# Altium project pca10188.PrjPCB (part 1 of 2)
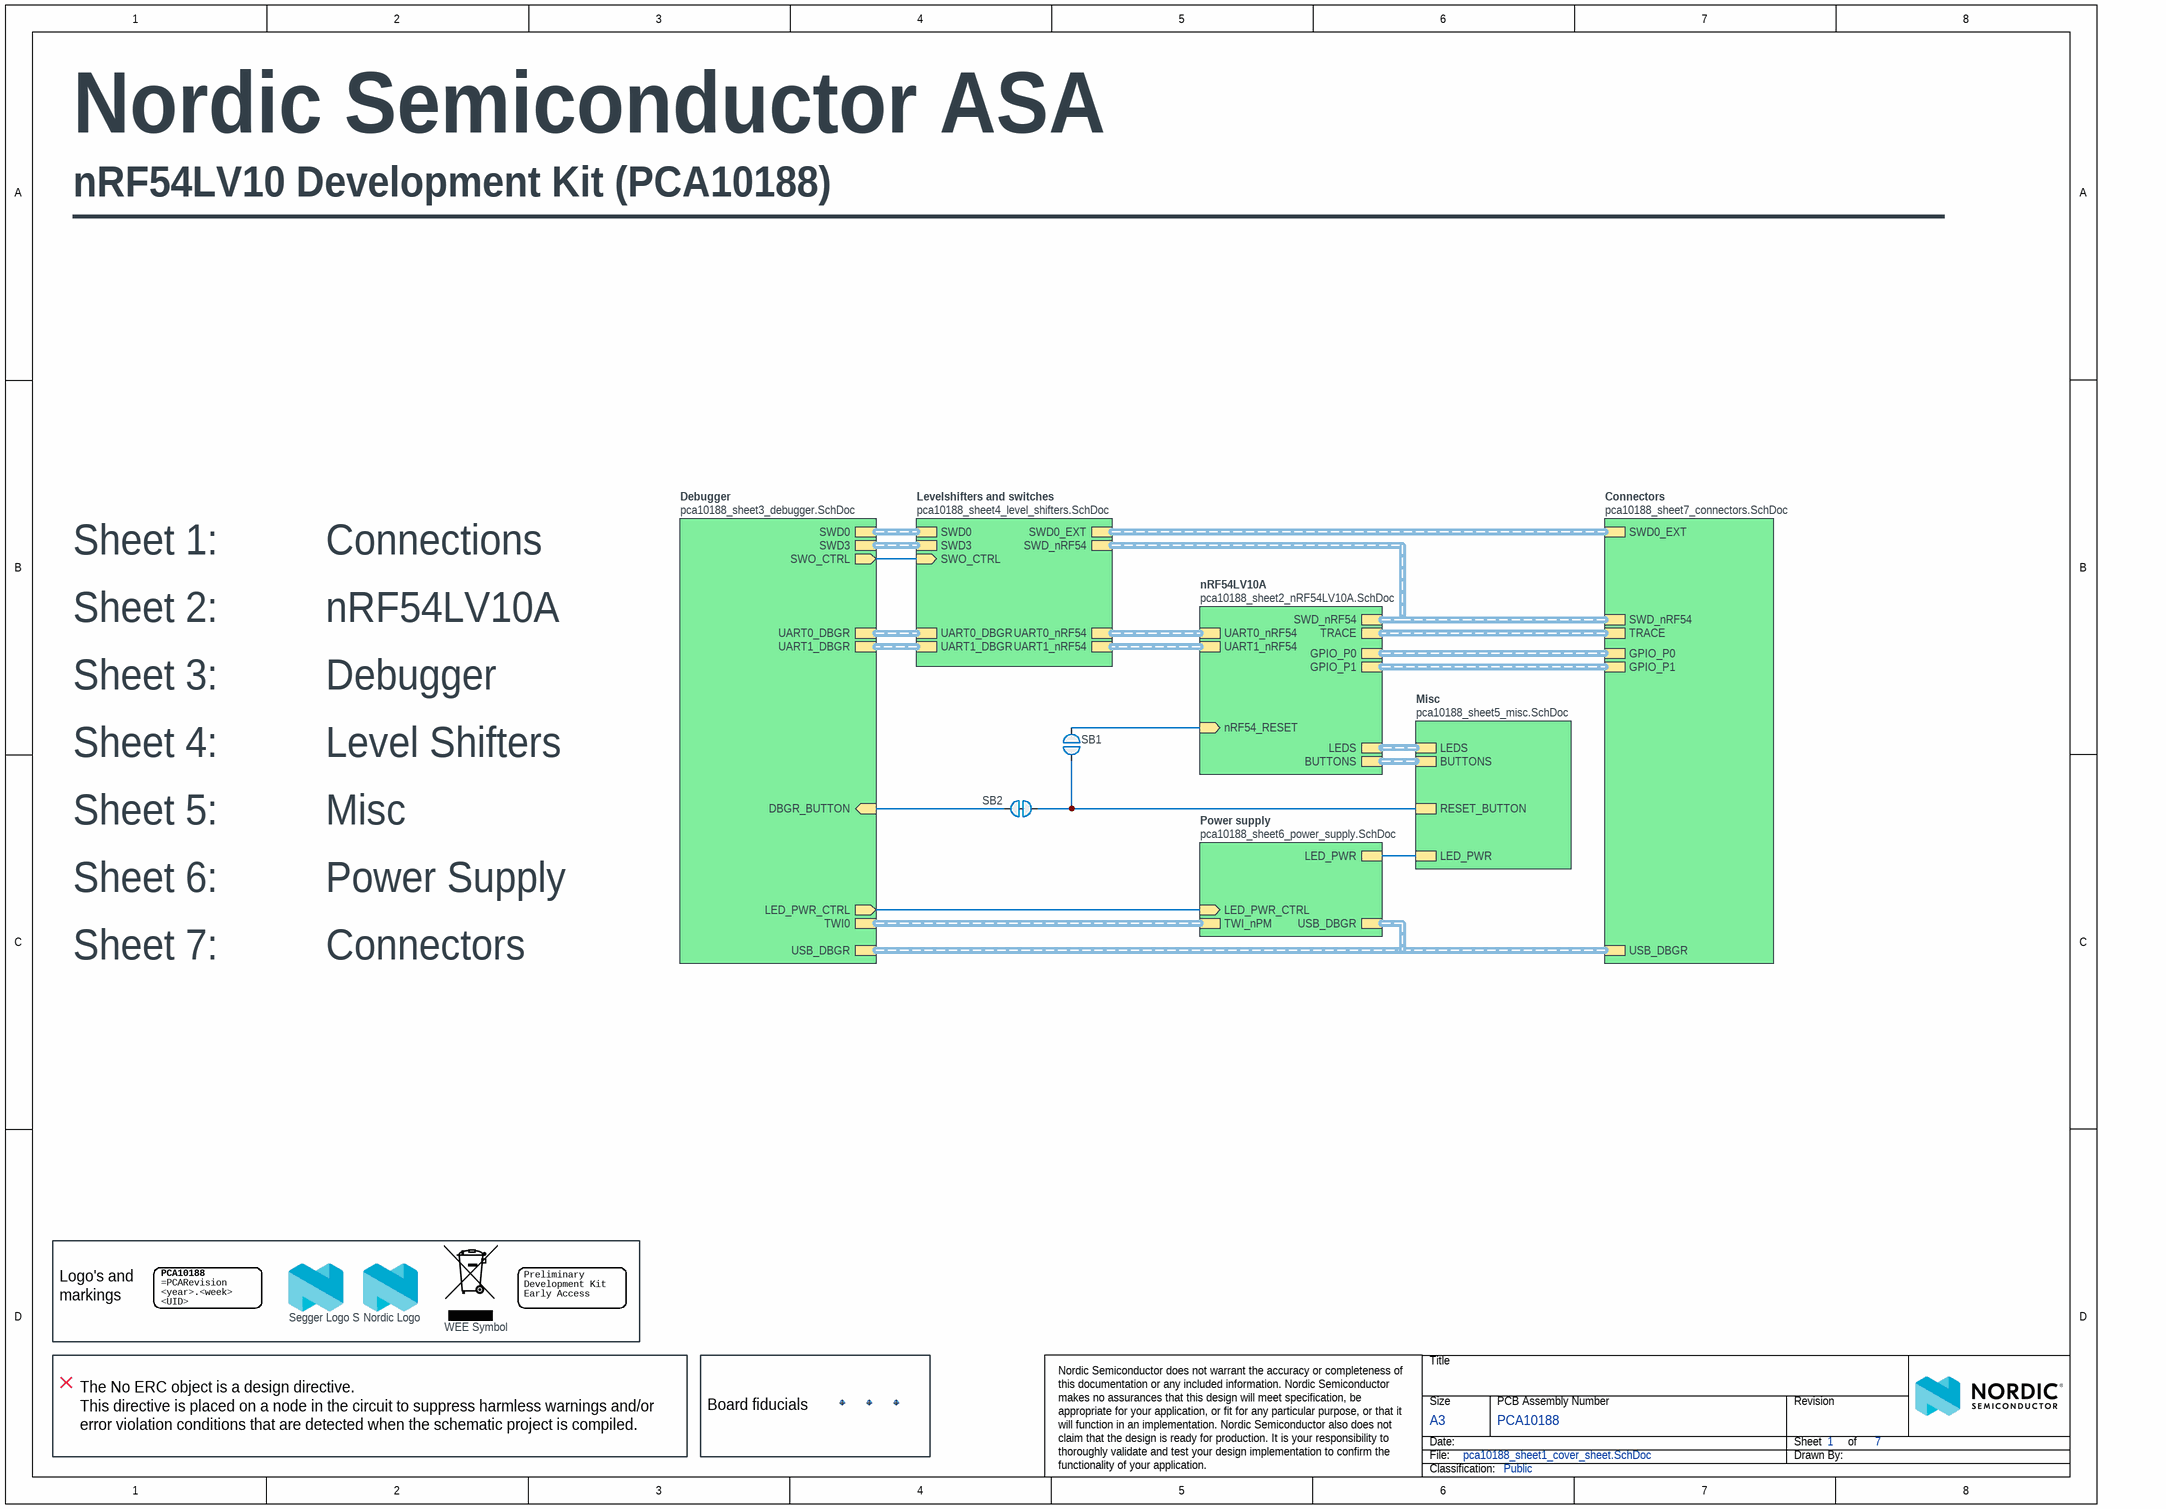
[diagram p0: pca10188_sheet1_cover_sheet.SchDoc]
BoardThickness: 1.6mm; BoardTitle: nRF54LV10-DK; Classification: Public; Compliance: RoHS, REACH, Halogen-Free; Designer: DABA; Dielectric: FR-4 IPC-4101/21; DrawnBy: =Designer; NrOfLayers: 4; Organization: Nordic Semiconductor; PCA_Name: =PCAName; PCAName: PCA10188; PCARevision: 0.7.0; PCBNumber: 400868; PCBRevision: 0038DABA; PCBStackup: 4001; ProductName: nRF54LV10-DK; SilkscreenColor: White; SoldermaskColor: Blue, IPC-SM-840 Class T; SurfaceFinish: ENIG
7 sheets, 211 parts. Net scope: hierarchical (ports join the sheet entries above them; power ports are global).
Board file: 400868.PcbDoc
Sheets:
  pca10188_sheet1_cover_sheet.SchDoc
    nRF54LV10A = pca10188_sheet2_nRF54LV10A.SchDoc
    Debugger = pca10188_sheet3_debugger.SchDoc
    Levelshifters and switches = pca10188_sheet4_level_shifters.SchDoc
    Misc = pca10188_sheet5_misc.SchDoc
    Power supply = pca10188_sheet6_power_supply.SchDoc
    Connectors = pca10188_sheet7_connectors.SchDoc

## Sheet pca10188_sheet1_cover_sheet.SchDoc: =BoardTitle+' - Connections'
size A3; Organization: Nordic Semiconductor; DocumentNumber: 1; Revision: 0.7.0; SheetNumber: 1; SheetTotal: 7; Author: DABA; CompanyName: Nordic Semiconductor; DrawnBy: DABA; DocumentSize: A4

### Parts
Fid1  Fiducial mark  [Fiducial]  (value not drawn)
Fid2  Fiducial mark  [Fiducial]  (value not drawn)
Fid3  Fiducial mark  [Fiducial]  (value not drawn)
LABEL1  12x12mm  [LabelSilk_12x12]  (value not drawn)
LABEL2  20x40mm  [LabelSilk_20x40]  (value not drawn)
LOGO1  Nordic Logo  [NORDIC_LOGO_LYING]  (no BOM)
LOGO2  WEE Symbol  [WEE_3x4.5mm]  (no BOM)
LOGO3  Segger Logo S  [SEGGER_LOGO_S]  (no BOM)
SB1  Solderbridge  [Solderbridge]  (value not drawn)  (no BOM)
SB2  Solderbridge  [Solderbridge_Shorted]  (value not drawn)  (net tie, no BOM)

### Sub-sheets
Connectors = pca10188_sheet7_connectors.SchDoc: SWD_nRF54 (harness SWD), TRACE (harness TRACE), SWD0_EXT (harness SWD), GPIO_P0 (harness GPIO_P0), GPIO_P1 (harness GPIO_P1), USB_DBGR (harness USB)
Debugger = pca10188_sheet3_debugger.SchDoc: DBGR_BUTTON (in), SWD0 (harness SWD), UART0_DBGR (harness UART_IMCU), USB_DBGR (harness USB), UART1_DBGR (harness UART_IMCU), TWI0 (harness TWI), SWD3 (harness SWD), LED_PWR_CTRL (out), SWO_CTRL (out)
Levelshifters and switches = pca10188_sheet4_level_shifters.SchDoc: SWD0 (harness SWD), SWD0_EXT (harness SWD), UART0_nRF54 (harness UART), UART1_nRF54 (harness UART), SWD3 (harness SWD), SWD_nRF54 (harness SWD), UART0_DBGR (harness UART_IMCU), UART1_DBGR (harness UART_IMCU), SWO_CTRL (in)
Misc = pca10188_sheet5_misc.SchDoc: BUTTONS (harness UI), LEDS (harness UI), RESET_BUTTON, LED_PWR
nRF54LV10A = pca10188_sheet2_nRF54LV10A.SchDoc: BUTTONS (harness UI), LEDS (harness UI), TRACE (harness TRACE), GPIO_P0 (harness GPIO_P0), UART0_nRF54 (harness UART), GPIO_P1 (harness GPIO_P1), UART1_nRF54 (harness UART), SWD_nRF54 (harness SWD), nRF54_RESET (in)
Power supply = pca10188_sheet6_power_supply.SchDoc: TWI_nPM (harness TWI), LED_PWR_CTRL (in), LED_PWR, USB_DBGR (harness USB)

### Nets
DBGR_BUTTON: SB2.2 ; sheet Debugger/DBGR_BUTTON
LED_PWR: sheet Misc/LED_PWR, sheet Power supply/LED_PWR
LED_PWR_CTRL: sheet Debugger/LED_PWR_CTRL, sheet Power supply/LED_PWR_CTRL
nRF54_NRESET: SB1.1 ; sheet nRF54LV10A/nRF54_RESET
RESET_BUTTON: SB1.2 SB2.1 ; sheet Misc/RESET_BUTTON
SWO_CTRL: sheet Debugger/SWO_CTRL, sheet Levelshifters and switches/SWO_CTRL

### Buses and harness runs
harness sheet Connectors/GPIO_P0 = sheet nRF54LV10A/GPIO_P0
harness sheet Connectors/GPIO_P1 = sheet nRF54LV10A/GPIO_P1
harness sheet Connectors/SWD0_EXT = sheet Levelshifters and switches/SWD0_EXT
harness sheet Connectors/SWD_nRF54 = sheet Levelshifters and switches/SWD_nRF54 = sheet nRF54LV10A/SWD_nRF54
harness sheet Connectors/TRACE = sheet nRF54LV10A/TRACE
harness sheet Connectors/USB_DBGR = sheet Debugger/USB_DBGR = sheet Power supply/USB_DBGR
harness sheet Debugger/SWD0 = sheet Levelshifters and switches/SWD0
harness sheet Debugger/SWD3 = sheet Levelshifters and switches/SWD3
harness sheet Debugger/TWI0 = sheet Power supply/TWI_nPM
harness sheet Debugger/UART0_DBGR = sheet Levelshifters and switches/UART0_DBGR
harness sheet Debugger/UART1_DBGR = sheet Levelshifters and switches/UART1_DBGR
harness sheet Levelshifters and switches/UART0_nRF54 = sheet nRF54LV10A/UART0_nRF54
harness sheet Levelshifters and switches/UART1_nRF54 = sheet nRF54LV10A/UART1_nRF54
harness sheet Misc/BUTTONS = sheet nRF54LV10A/BUTTONS
harness sheet Misc/LEDS = sheet nRF54LV10A/LEDS

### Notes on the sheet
- Nordic Semiconductor ASA
- nRF54LV10 Development Kit (PCA10188)
- ________________________________________________________________
- Sheet 1:          Connections
- Sheet 2:          nRF54LV10A
- Sheet 3:          Debugger
- Sheet 4:          Level Shifters
- Sheet 5:          Misc
- Sheet 6:          Power Supply
- Sheet 7:          Connectors
- (near LABEL1) Logo's and markings
- The No ERC object is a design directive.
  This directive is placed on a node in the circuit to suppress harmless warnings and/or error violation conditions that are detected when the schematic project is compiled.
- (near Fid1) Board fiducials

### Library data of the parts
Fid1-Fid3 = Fid-Mark: Manufacturer: N.A.; Part number NEMS: 100500073; Value: N.A.; Pad Count: 1; Component Status: Active; System: Connector
LABEL1 = Label_12x12: PCA version label, stick-on, 12x12mm; Manufacturer: Ellco Etikett; Manufacturer Part Number: A33512‐01; Part number NEMS: 101200028; Component Status: Active; Pad Count: 0; Note: N.A.
LABEL2 = Label_20x40: Early Access Label; Manufacturer: NA; Part number NEMS: 101200035; Component Status: Active; Pad Count: 0; Note: N.A.
LOGO1 = Nordic Logo lying: Manufacturer: N.A.; Part number NEMS: 101100001; Component Status: Active; Pad Count: 0
LOGO2 = WEEE Symbol 3x4.5mm: WEEE Directive symbol; Manufacturer: N.A.; Part number NEMS: 101100006; Component Status: Active; Pad Count: 0
LOGO3 = Segger Logo S: Segger logo, small size; Manufacturer: N.A.; Part number NEMS: 101100004; Component Status: Active; Pad Count: 0
SB1 = Solderbridge: Manufacturer: N.A.; Part number NEMS: 100500458; Pad Count: 2; Component Status: Active; System: Connector
SB2 = Solderbridge Shorted: Shorted Solderbridge; Manufacturer: N.A.; Part number NEMS: 100500459; Pad Count: 2; Component Status: Active; System: Connector

## Sheet pca10188_sheet2_nRF54LV10A.SchDoc: =BoardTitle+' - nRF54LV10A'
size A3; Organization: Nordic Semiconductor; DocumentNumber: 2; Revision: 0.7.0; SheetNumber: 2; SheetTotal: 7; Author: DABA; CompanyName: Nordic Semiconductor; DrawnBy: DABA; DocumentSize: A4
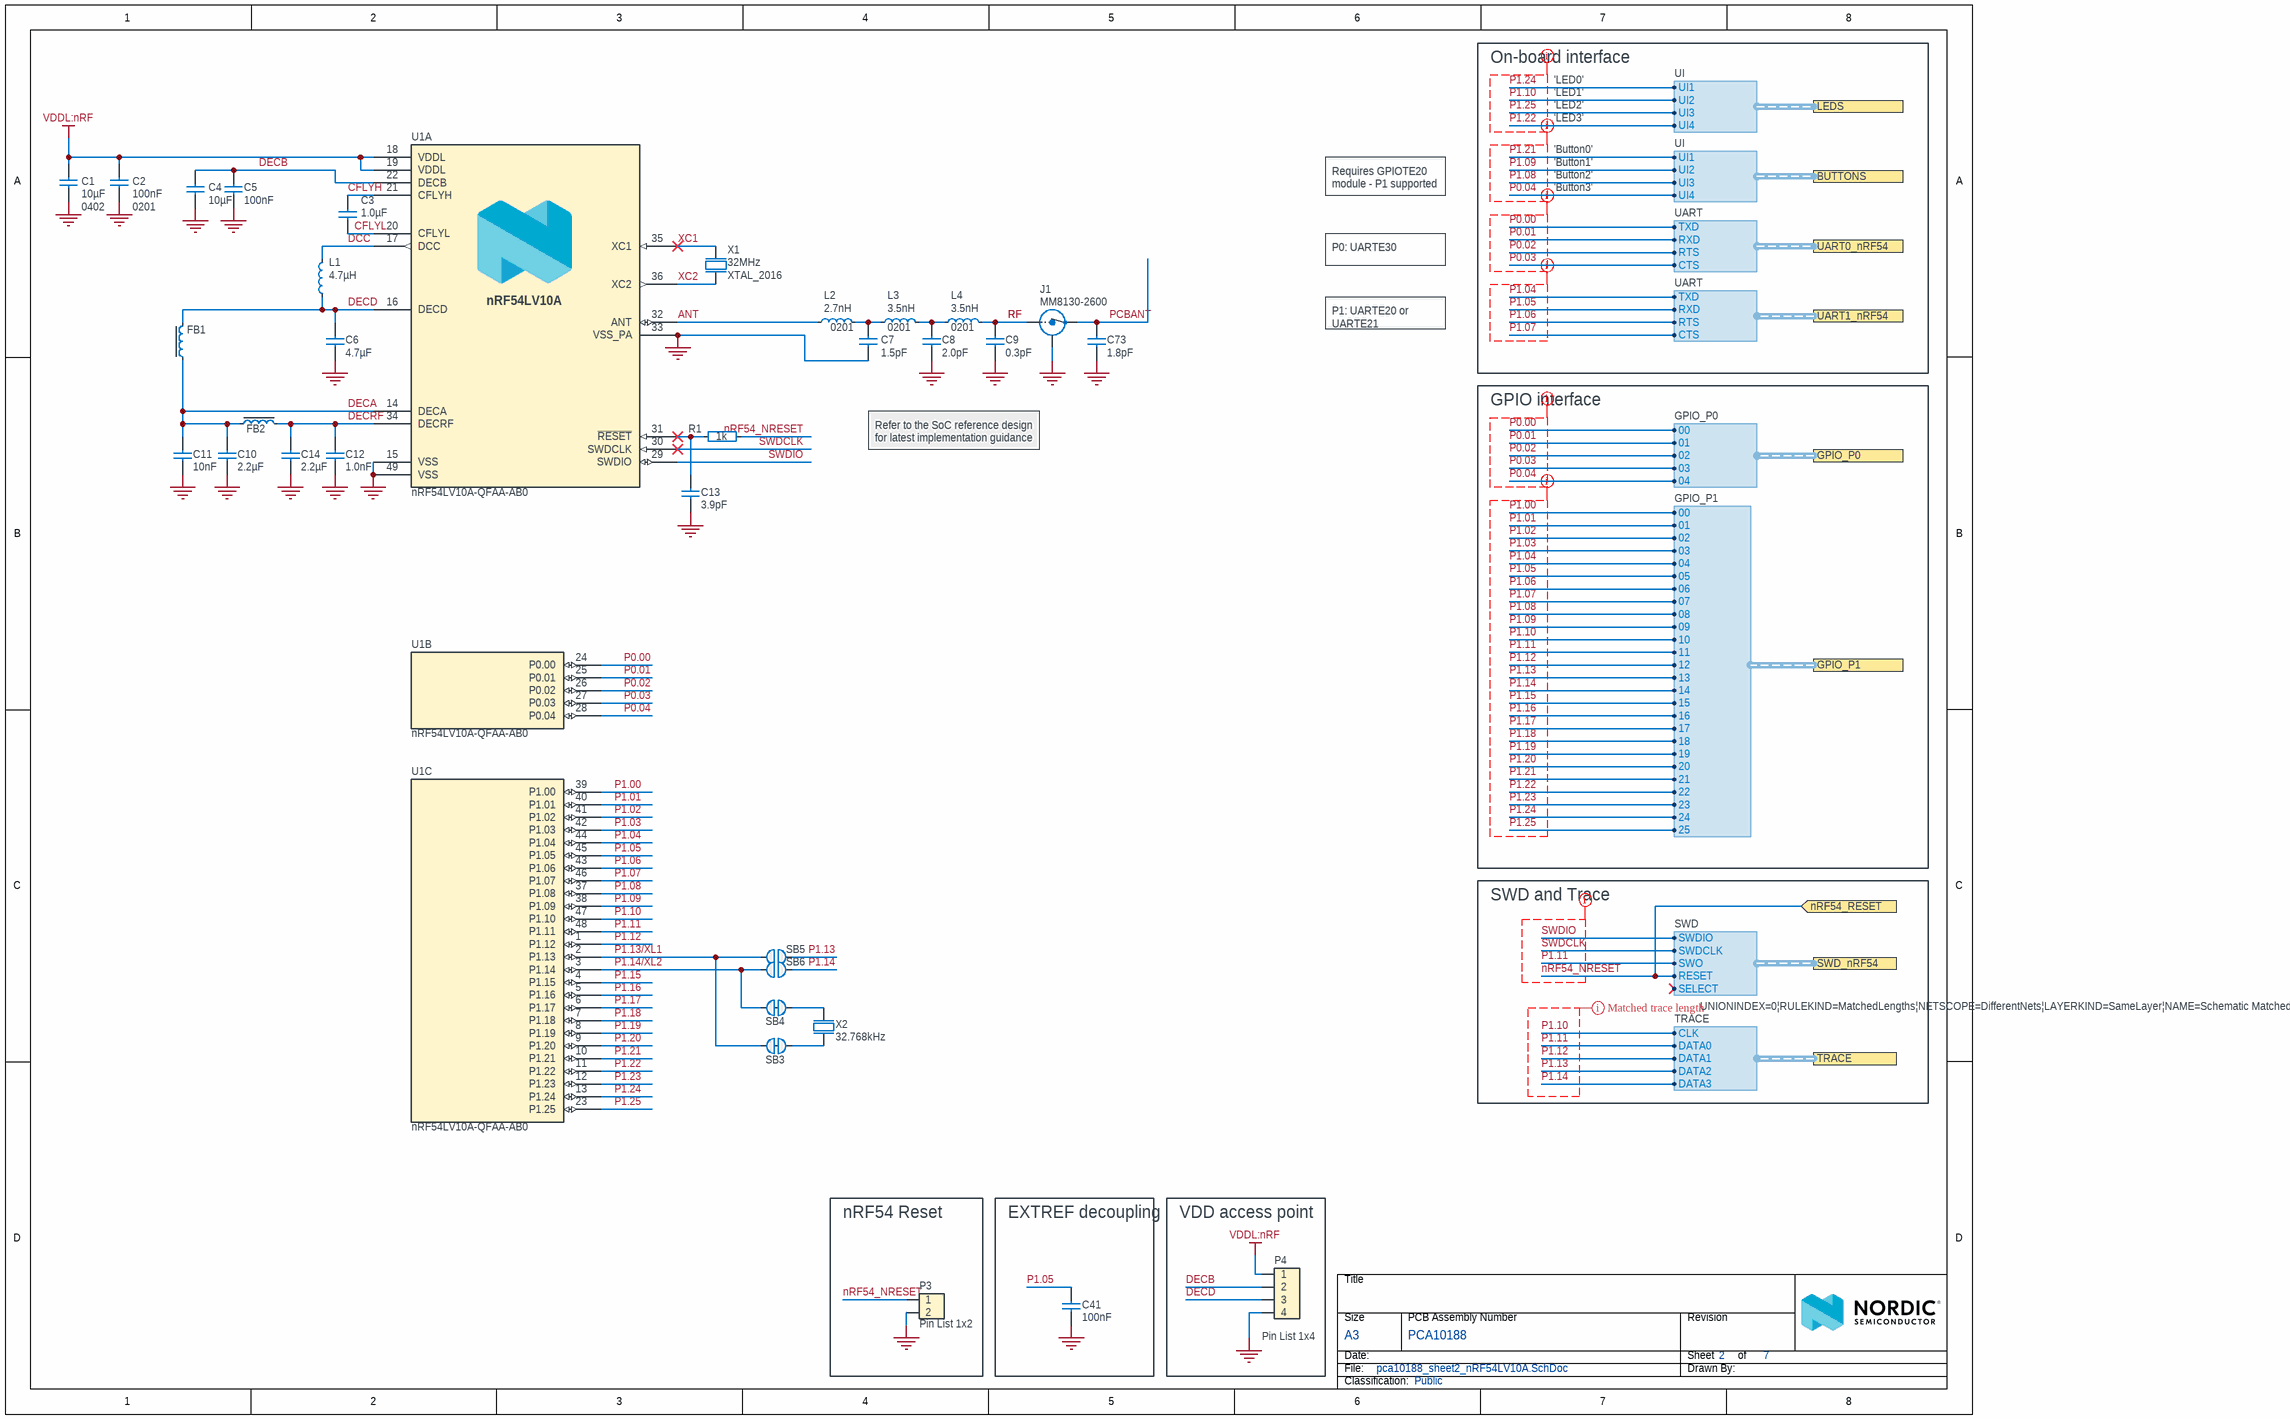
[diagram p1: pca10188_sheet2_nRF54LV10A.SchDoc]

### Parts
C1  10µF  Footprint Doc: 0402  [CAPC1005X04L]
C2  100nF  Footprint Doc: 0201  [CAPC0603X03L_C]
C3  1.0µF  [CAPC0603X03L_C]
C4  10µF  [CAPC1005X04L]
C5  100nF  [CAPC0603X03L_C]
C6  4.7µF  [CAPC0603X03L_C]
C7  1.5pF  [CAPC0603X03L_C]
C8  2.0pF  [CAPC0603X03L_C]
C9  0.3pF  [CAPC0603X03L_C]
C10  2.2µF  [CAPC0603X03L_C]
C11  10nF  [CAPC0603X03L_C]
C12  1.0nF  [CAPC0603X03L_C]
C13  3.9pF  [CAPC0603X03L_C]
C14  2.2µF  [CAPC0603X03L_C]
C41  100nF  [CAPC1005X04L]
C73  1.8pF  [CAPC0603X03L_C]
FB1  120R/0.2A  [INDC0603X03L_C]  (value not drawn)
FB2  120R/0.2A  [INDC0603X03L_C]  (value not drawn)
J1  MM8130-2600  [COAXIAL-SWF]
L1  4.7µH  [INDC1608X06L]
L2  2.7nH  Footprint Doc: 0201  [INDC0603X03L_C]
L3  3.5nH  Footprint Doc: 0201  [INDC0603X03L_C]
L4  3.5nH  Footprint Doc: 0201  [INDC0603X03L_C]
P3  Pin List 1x2  [LIST_1x2]
P4  Pin List 1x4  [LIST_1x4]
R1  1k  [RESC0603X03L_C]
SB3  Solderbridge  [Solderbridge_SHORTED_0.4]  (value not drawn)  (net tie, no BOM)
SB4  Solderbridge  [Solderbridge_SHORTED_0.4]  (value not drawn)  (net tie, no BOM)
SB5  Solderbridge  [Solderbridge_0.4]  (value not drawn)  (no BOM)
SB6  Solderbridge  [Solderbridge_0.4]  (value not drawn)  (no BOM)
U1  nRF54LV10A-QFAA-AB0  [QFN49P40_600x600x90L40x20T460N]  (parts A,B,C of 3)
X1  32MHz  Footprint Doc: XTAL_2016  [BT-XTAL_2016]
X2  32.768kHz  [XTAL_2012]

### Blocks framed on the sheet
nRF54 Reset: P3
EXTREF decoupling: C41
VDD access point: P4

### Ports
BUTTONS (harness UI), GPIO_P0 (harness GPIO_P0), GPIO_P1 (harness GPIO_P1), LEDS (harness UI), nRF54_RESET (in), SWD_nRF54 (harness SWD), TRACE (harness TRACE), UART0_nRF54 (harness UART), UART1_nRF54 (harness UART)

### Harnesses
SWD: SWDIO, SWDCLK, SWO, RESET, SELECT
UART: RTS, CTS, RXD, TXD
GPIO_P1: 00, 01, 02, 03, 04, 05, 06, 07, 08, 09, 10, 11, 12, 13, 14, 15, 21, 22, 16, 23, 17, 24, 18, 25, 19, 20
GPIO_P0: 02, 03, 04, 00, 01
TRACE: CLK, DATA0, DATA1, DATA3, DATA2
UI: UI2, UI1, UI3, UI4

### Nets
GND: C1.1 C2.1 C4.1 C5.2 C6.1 C7.1 C8.1 C9.1 C10.1 C11.1 C12.1 C13.1 C14.1 C41.1 C73.1 J1.2(Shield) P3.2 P4.4 U1.15(VSS) U1.33(VSS_PA) U1.49(VSS) X1.2(GND) X1.4(GND)
VDDL:nRF: C1.2 C2.2 P4.1 U1.18(VDDL) U1.19(VDDL)
ANT: L2.1 U1.32(ANT)
CFLYH: C3.2 U1.21(CFLYH)
CFLYL: C3.1 U1.20(CFLYL)
DCC: L1.1 U1.17(DCC)
DECA: C10.2 C11.2 FB1.2 FB2.2 U1.14(DECA)
DECB: C4.2 C5.1 P4.2 U1.22(DECB)
DECD: C6.2 FB1.1 L1.2 P4.3 U1.16(DECD)
DECRF: C12.2 C14.2 FB2.1 U1.34(DECRF)
nRF54_NRESET: P3.1 R1.2 ; port nRF54_RESET, port SWD_nRF54.RESET
P0.00: U1.24(P0.00) ; port UART0_nRF54.TXD, port GPIO_P0.00
P0.01: U1.25(P0.01) ; port UART0_nRF54.RXD, port GPIO_P0.01
P0.02: U1.26(P0.02) ; port UART0_nRF54.RTS, port GPIO_P0.02
P0.03: U1.27(P0.03) ; port UART0_nRF54.CTS, port GPIO_P0.03
P0.04: U1.28(P0.04) ; port GPIO_P0.04, port BUTTONS.UI4
P1.00: U1.39(P1.00) ; port GPIO_P1.00
P1.01: U1.40(P1.01) ; port GPIO_P1.01
P1.02: U1.41(P1.02) ; port GPIO_P1.02
P1.03: U1.42(P1.03) ; port GPIO_P1.03
P1.04: U1.44(P1.04) ; port GPIO_P1.04, port UART1_nRF54.TXD
P1.05: C41.2 U1.45(P1.05) ; port GPIO_P1.05, port UART1_nRF54.RXD
P1.06: U1.43(P1.06) ; port GPIO_P1.06, port UART1_nRF54.RTS
P1.07: U1.46(P1.07) ; port GPIO_P1.07, port UART1_nRF54.CTS
P1.08: U1.37(P1.08) ; port GPIO_P1.08, port BUTTONS.UI3
P1.09: U1.38(P1.09) ; port GPIO_P1.09, port BUTTONS.UI2
P1.10: U1.47(P1.10) ; port GPIO_P1.10, port TRACE.CLK, port LEDS.UI2
P1.11: U1.48(P1.11) ; port SWD_nRF54.SWO, port GPIO_P1.11, port TRACE.DATA0
P1.12: U1.1(P1.12) ; port GPIO_P1.12, port TRACE.DATA1
P1.13: SB5.2 ; port GPIO_P1.13, port TRACE.DATA2
P1.13/XL1: SB3.1 SB5.1 U1.2(P1.13)
P1.14: SB6.2 ; port GPIO_P1.14, port TRACE.DATA3
P1.14/XL2: SB4.1 SB6.1 U1.3(P1.14)
P1.15: U1.4(P1.15) ; port GPIO_P1.15
P1.16: U1.5(P1.16) ; port GPIO_P1.16
P1.17: U1.6(P1.17) ; port GPIO_P1.17
P1.18: U1.7(P1.18) ; port GPIO_P1.18
P1.19: U1.8(P1.19) ; port GPIO_P1.19
P1.20: U1.9(P1.20) ; port GPIO_P1.20
P1.21: U1.10(P1.21) ; port GPIO_P1.21, port BUTTONS.UI1
P1.22: U1.11(P1.22) ; port GPIO_P1.22, port LEDS.UI4
P1.23: U1.12(P1.23) ; port GPIO_P1.23
P1.24: U1.13(P1.24) ; port GPIO_P1.24, port LEDS.UI1
P1.25: U1.23(P1.25) ; port GPIO_P1.25, port LEDS.UI3
PCBANT: C73.2 J1.3(OUT)
RF: C9.2 J1.1(IN) L4.2
SWDCLK: U1.30(SWDCLK) ; port SWD_nRF54.SWDCLK
SWDIO: U1.29(SWDIO) ; port SWD_nRF54.SWDIO
XC1: U1.35(XC1) X1.1(inp)
XC2: U1.36(XC2) X1.3(out)
NetC7_2: C7.2 L2.2 L3.1
NetC8_2: C8.2 L3.2 L4.1
NetC13_2: C13.2 R1.1 U1.31(~{RESET})
NetSB3_2: SB3.2 X2.2(out)
NetSB4_2: SB4.2 X2.1(inp)

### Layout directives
net class TRACE; rule Matched Net Lengths [Delay Tolerance = 500ps]: P1.10, P1.11, P1.12, P1.13, P1.14
net class LEDS: P1.10, P1.22, P1.24, P1.25
net class UART0: P0.00, P0.01, P0.02, P0.03
net class UART1: P1.04, P1.05, P1.06, P1.07
net class BUTTONS: P0.04, P1.08, P1.09, P1.21
net class SWD_nRF54: nRF54_NRESET, P1.11, SWDCLK, SWDIO
net class GPIO_P0: P0.00, P0.01, P0.02, P0.03, P0.04
net class GPIO_P1: P1.00, P1.01, P1.02, P1.03, P1.04, P1.05, P1.06, P1.07, P1.08, P1.09, P1.10, P1.11, P1.12, P1.13, P1.14, P1.15, P1.16, P1.17, P1.18, P1.19, P1.20, P1.21, P1.22, P1.23, P1.24, P1.25

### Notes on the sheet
- On-board interface
- 'LED1'
- 'LED0'
- 'LED2'
- 'LED3'
- 'Button1'
- 'Button0'
- Requires GPIOTE20 module - P1 supported
- 'Button2'
- 'Button3'
- P0: UARTE30
- P1: UARTE20 or UARTE21
- GPIO interface
- Refer to the SoC reference design for latest implementation guidance
- SWD and Trace

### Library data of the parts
C1 C4 = C0402-10µF-6.3V-X6S: Capacitor, X6S, ±20%, 6.3V; Manufacturer: N.A.; Part number NEMS: 100200478; Component Status: Active; Pad Count: 2
C2 = C0201-100n-10V-X7R: Capacitor, X7R, ±10%, 100nF, 10V; Manufacturer: N.A.; Part number NEMS: 100200469; Component Status: Active; Pad Count: 2
C3 = C0201-1µ0-6.3V: Capacitor, Ceramic, X5R, ±20%, 6.3V; Manufacturer: Murata; Manufacturer Part Number: GRM033R60J105MEA2D; Part number NEMS: 100200387; Component Status: Active; Pad Count: 2; Artikkelnr Noca: N.A.
C5 = C0201-100n-10V-X7R: Capacitor, X7R, ±10%; Manufacturer: N.A.; Part number NEMS: 100200469; Note: 10V; Pad Count: 2; Component Status: Active
C6 = C0201-4.7µ-6V3-X5R-GRM035R60J475ME15J: Capacitor, Ceramic, X5R, ±20%, 6.3V; Manufacturer: Murata; Part number NEMS: 100200685; Component Status: Active; Pad Count: 2; Note: -55°C ~ 85°C; Artikkelnr Noca: N.A.
C7 = C0201-1.5p-25V-NP0-GJM0335C1E1R5WB01: Capacitor, NP0, ±0.05pF, 25V, High Q; Manufacturer: Murata; Part number NEMS: 100200477; Component Status: Active; Pad Count: 2; Artikkelnr Noca: N.A.
C8 = C0201-2.0p-HQ-Murata: Capacitor, NP0, ±0.05pF, 25V; Manufacturer: Murata; Manufacturer Part Number: GJM0335C1E2R0WB01; Part number IPS: 00000001775; Part number NEMS: 100200419; Component Status: Active; Pad Count: 2; Artikkelnr Noca: N.A.
C9 = C0201-0.3p-50V-GRM0335C1HR30BA01: Capacitor, C0G, ±0.1pF, 50V; Manufacturer: Murata; Part number NEMS: 100200650; Component Status: Active; Pad Count: 2; Artikkelnr Noca: N.A.
C10 C14 = C0201-2µ2-2.5V-X6T-GRM033D80E225ME47D: Capacitor, Ceramic, 2.2µF 2.5V X6T 0201,±20%; Manufacturer: Murata; Part number NEMS: 100200527; Component Status: Active; Pad Count: 2; Note: 2.5V, 20%, X6T; Artikkelnr Noca: N.A.
C11 = C0201-10n-6.3V-X7R: Capacitor, X7R, 6.3V; Manufacturer: Murata; Manufacturer Part Number: GRM033R70J103KA01D; Part number NEMS: 100200407; Component Status: Active; Pad Count: 2; Artikkelnr Noca: N.A.
C12 = C0201-1n0: Capacitor, X7R, ±10%, 25V; Manufacturer: N.A.; Part number IPS: 00000003206; Part number NEMS: 100200056; Component Status: Active; Pad Count: 2; Note: 16V
C13 = C0201-3.9p: Chip Cap 0201; Manufacturer: N.A.; Part number NEMS: 100200024,100200424; Component Status: Active; Pad Count: 2; Note: Chip Cap 1%
C41 = C0402-100n: Capacitor, X7R, ±10%; Manufacturer: N.A.; Part number IPS: 00000005296; Part number NEMS: 100200184; Component Status: Active; Pad Count: 2; Note: 16V; Artikkelnr Noca: 20039200
C73 = C0201-1p8-50V-COG-GJM0335C1H1R8BB01: CAP CER 1.8PF 50V C0G/NP0 0201; Manufacturer: Murata; Part number NEMS: 100200681; Pad Count: 2; Note: 50V, ±0,1pF; Artikkelnr Noca: N.A.; Component Status: Active
FB1 FB2 = FB0201-120R@100M-200mA-BLM03AG121SN1D: Ferrite Bead, 120 Ohm @ 100MHz, 200mA, 500 mOhm Max; Manufacturer: Murata; Part number NEMS: 100300419; Component Status: Active; Pad Count: 2; Artikkelnr Noca: N.A.
J1 = MM8130-2600: Coaxial Connector with Switch; Manufacturer: Murata; Part number IPS: 00000009955; Part number Norautron: 26030338; Part number NEMS: 100500400; Component Status: Active; Pad Count: 3; Note: N.A.; Artikkelnr Noca: 55029011
L1 = L0603-4µ7-MLZ1608M4R7WT000: Inductor, 120mA, ±20%, 0.65R; Manufacturer: TDK Corporation; Part number NEMS: 100300440; Component Status: Active; Pad Count: 2; Note: Power Inductor ±20%; Artikkelnr Noca: N.A.
L2 = L0201-2n7-HQ-Murata: Inductor, 600mA, ±0.1ｎH, 120mOhm; Manufacturer: Murata; Manufacturer Part Number: LQP03HQ2N7B02; Part number IPS: 00000001753; Part number NEMS: 100300214; Component Status: Active; Pad Count: 2; Note: -55°C ~ 125°C; Artikkelnr Noca: N.A.
L3 L4 = L0201-3n5-HQ-Murata: Inductor, 500mA, ±0.1ｎH, 170mOhm; Manufacturer: Murata; Manufacturer Part Number: LQP03HQ3N5B02; Part number NEMS: 100300222; Component Status: Active; Pad Count: 2; Note: -55°C ~ 125°C; Artikkelnr Noca: N.A.
P3 = Pin List 1x2: Pin List 1x2, 2.54mm (100mil); Manufacturer: N.A.; Part number NEMS: 100500297; Component Status: Active; Pad Count: 2; Artikkelnr Noca: 56019040; System: Connector
P4 = Pin List 1x4: Pin List 1x4, 2.54mm (100mil); Manufacturer: N.A.; Part number NEMS: 100500309; Component Status: Active; Pad Count: 4; Artikkelnr Noca: 56019092; System: Connector
R1 = R0201-1k0: Resistor, ±1%, 0.05W; Manufacturer: N.A.; Part number IPS: 00000005786; Part number NEMS: 100100043; Component Status: Active; Pad Count: 2; Note: Chip Res 1%
SB3 SB4 = Solderbridge Shorted 0.4mm: Shorted Solderbridge; Manufacturer: N.A.; Part number NEMS: 100500561; Component Status: Active; Pad Count: 2; System: Connector
SB5 SB6 = Solderbridge 0.4mm: Manufacturer: N.A.; Part number NEMS: 100500560; Component Status: Active; Pad Count: 2; System: Connector
U1 = nRF54LV10A-QFAA-AB0: Multi-protocol Bluetooth Low Energy, IEEE 802.15.4 and 2.4GHz proprietary Wireless MCU; Manufacturer: Nordic Semiconductor; Part number NEMS: 102000385; Component Status: Active; Pad Count: 49; Note: N.A.
X1 = XTAL_SMD2016_32MHz_8pF_Kyocera: XTAL SMD 2016, 32MHz, Cl=8pF, Tot: ±40ppm; Manufacturer Part Number: CX2016DB32000D0WZRC1; Part number IPS: 00000007827; Part number Norautron: 26511136; Part number NEMS: 101600039; Component Status: Active; Pad Count: 4; Note: XTAL SMD 32.000MHz; Artikkelnr Noca: 22010022
X2 = XTAL_SMD2012_32.768kHz_9pF_TXC: XTAL SMD 2012, 32.768kHz, 9pF, ±20ppm; Manufacturer: TXC Corporation; Manufacturer Part Number: 9HT11-32.768KDZC-T; Part number NEMS: 101600107; Component Status: Active; Pad Count: 2; Note: XTAL SMD 32.768kHz; Artikkelnr Noca: N.A.

## Sheet pca10188_sheet3_debugger.SchDoc: =BoardTitle+' - Debugger'
size A3; Organization: Nordic Semiconductor; DocumentNumber: 3; Revision: 0.7.0; SheetNumber: 3; SheetTotal: 7; Author: DABA; CompanyName: Nordic Semiconductor; DrawnBy: DABA; DocumentSize: A4
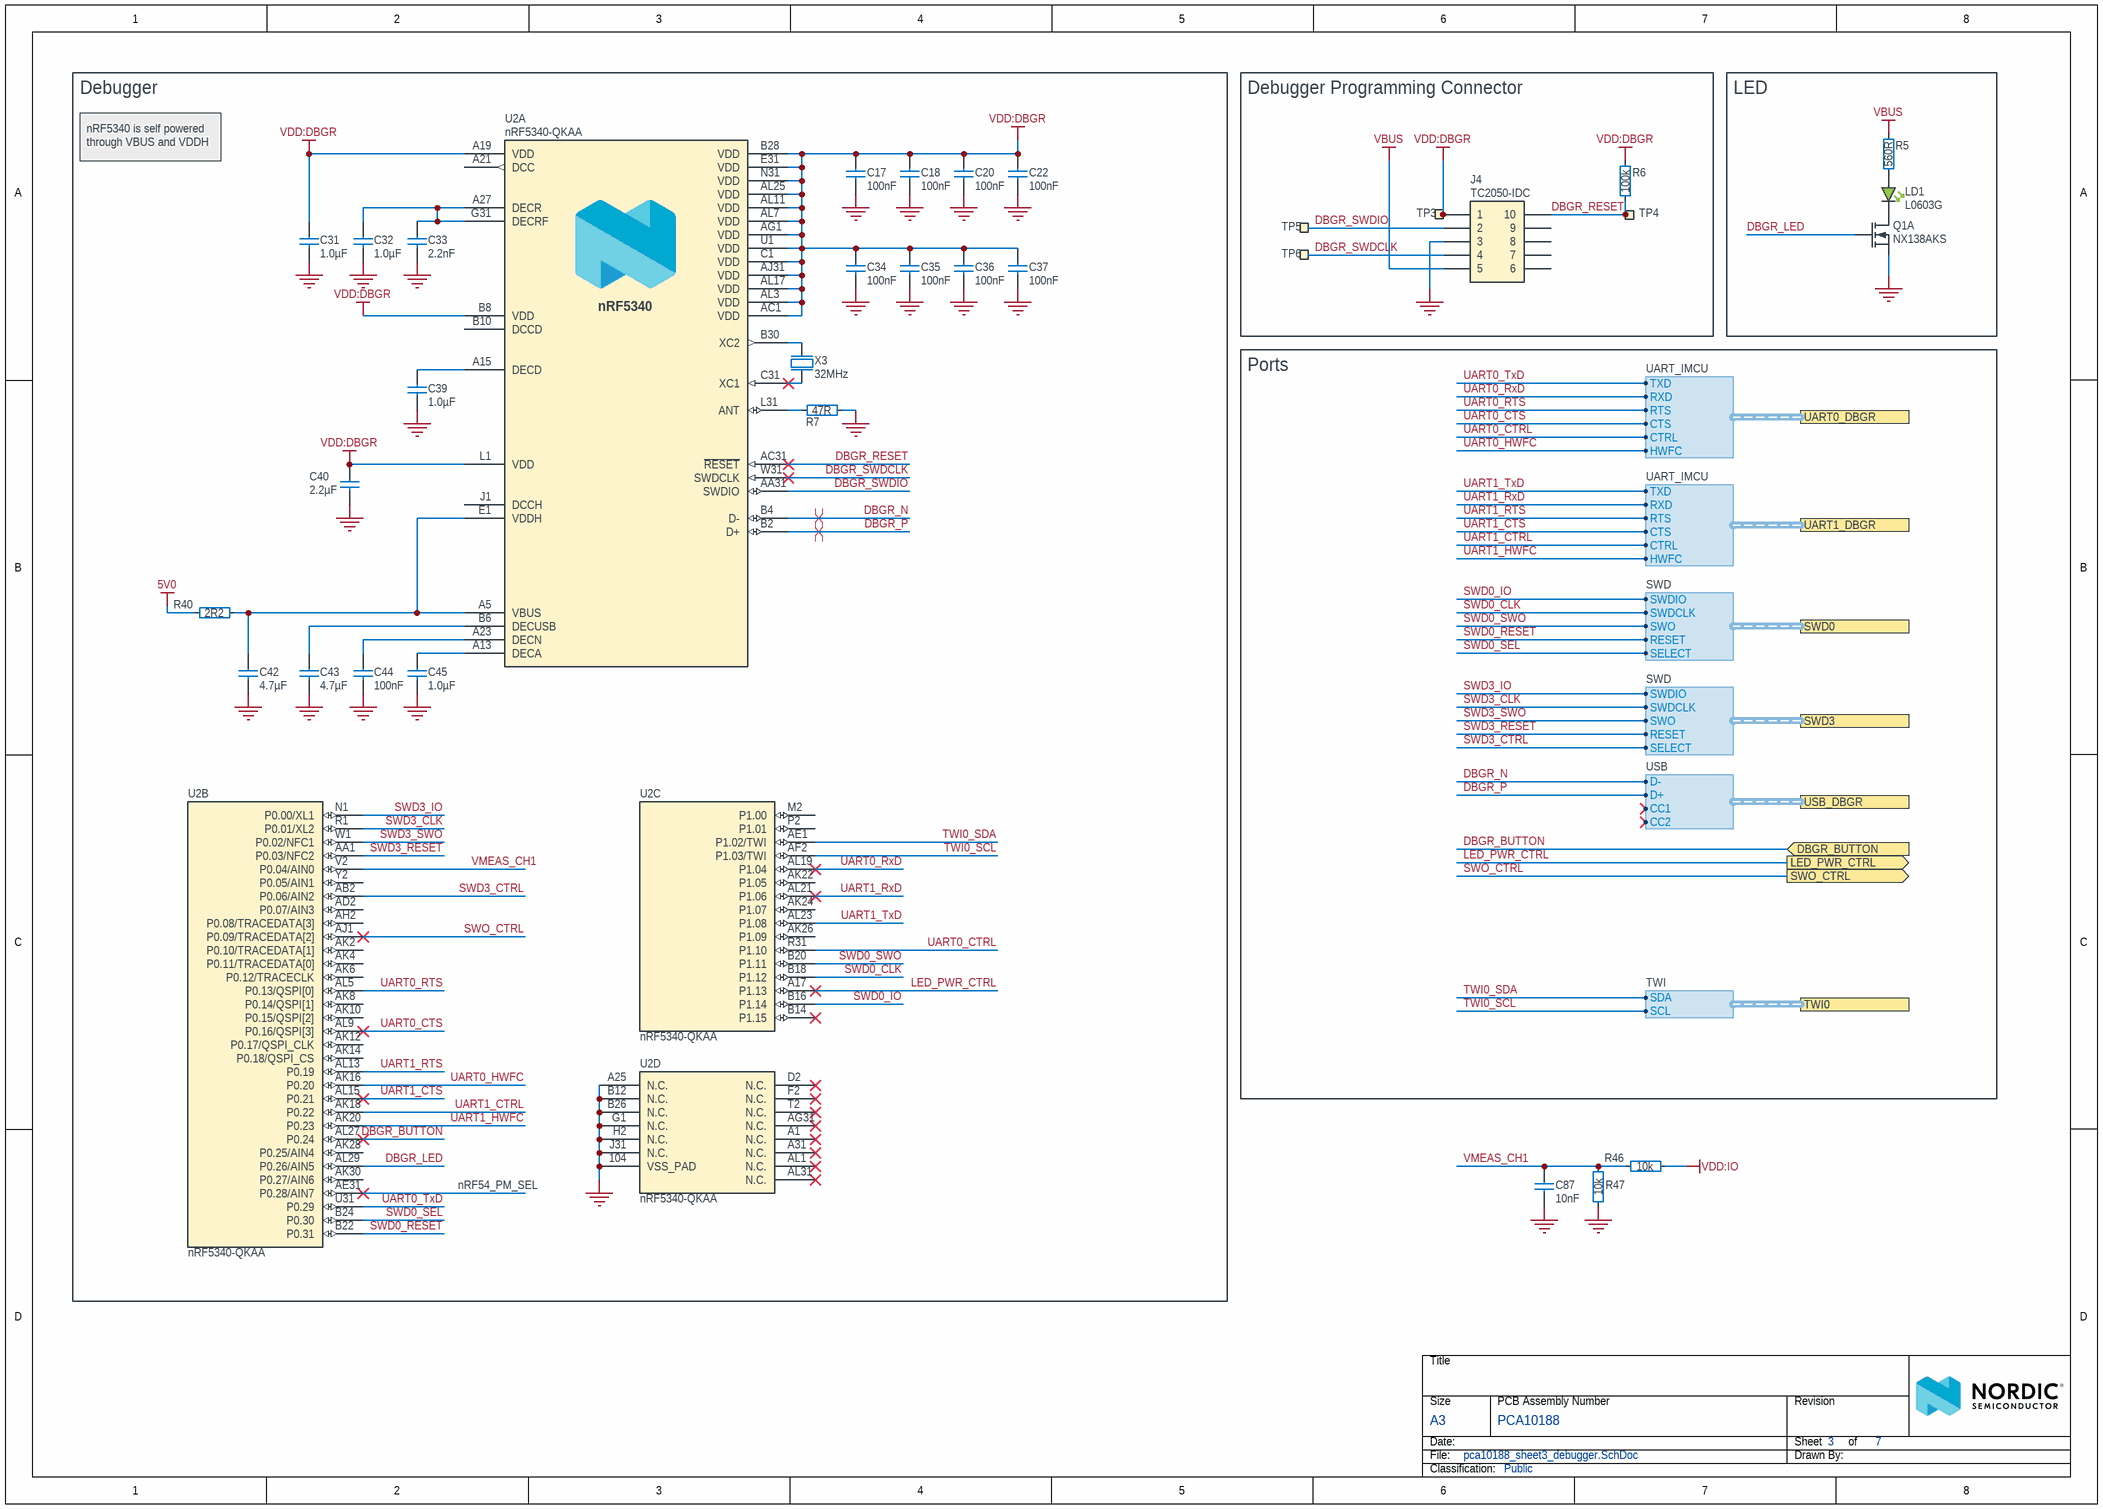
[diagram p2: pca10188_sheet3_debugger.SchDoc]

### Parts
C17  100nF  [CAPC0603X03L_C]
C18  100nF  [CAPC0603X03L_C]
C20  100nF  [CAPC0603X03L_C]
C22  100nF  [CAPC0603X03L_C]
C31  1.0µF  [CAPC1005X04L]
C32  1.0µF  [CAPC1005X04L]
C33  2.2nF  [CAPC0603X03L_C]
C34  100nF  [CAPC0603X03L_C]
C35  100nF  [CAPC0603X03L_C]
C36  100nF  [CAPC0603X03L_C]
C37  100nF  [CAPC0603X03L_C]
C39  1.0µF  [CAPC1005X04L]
C40  2.2µF  [CAPC1608X06L]
C42  4.7µF  [CAPC1608X06L]
C43  4.7µF  [CAPC1608X06L]
C44  100nF  [CAPC0603X03L_C]
C45  1.0µF  [CAPC1005X04L]
C87  10nF  [CAPC0603X03L_C]
J4  TC2050-IDC  [TC2050-IDC-NLFP]  (no BOM)
LD1  L0603G  [LED_0603_G]
Q1  NX138AKS  [TSSOP6]  (part A of 2)
R5  560R  [RESC0603X03L_C]
R6  100k  [RESC0603X03L_C]
R7  47R  [RESC0603X03L_C]
R40  2R2  [RESC1005X04L]
R46  10k  [RESC0603X03L_C]
R47  10k  [RESC0603X03L_C]
TP3  Ø1.5mm,SMD  [TP_SMD_D1.5mm]  (value not drawn)  (no BOM)
TP4  Ø1.5mm,SMD  [TP_SMD_D1.5mm]  (value not drawn)  (no BOM)
TP5  Ø1.5mm,SMD  [TP_SMD_D1.5mm]  (value not drawn)  (no BOM)
TP6  Ø1.5mm,SMD  [TP_SMD_D1.5mm]  (value not drawn)  (no BOM)
U2  nRF5340-QKAA  [AQFN40P700X700X85_HS-99N]  (parts A,B,C,D of 4)
X3  32MHz  [BT-XTAL_2016]

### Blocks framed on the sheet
Debugger: C17 C18 C20 C22 C31-C37 C39 C40 C42-C45 R7 R40 U2 X3
Debugger Programming Connector: J4 R6 TP3-TP6
LED: LD1 Q1 R5

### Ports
DBGR_BUTTON (in), LED_PWR_CTRL (out), SWD0 (harness SWD), SWD3 (harness SWD), SWO_CTRL (out), TWI0 (harness TWI), UART0_DBGR (harness UART_IMCU), UART1_DBGR (harness UART_IMCU), USB_DBGR (harness USB)

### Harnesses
SWD: SWDIO, SWDCLK, SWO, RESET, SELECT
UART_IMCU: RTS, CTS, RXD, TXD, HWFC, CTRL
TWI: SCL, SDA
USB: D+, D-, CC1, CC2

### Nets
5V0: R40.2
GND: C17.2 C18.2 C20.2 C22.2 C31.2 C32.1 C33.2 C34.2 C35.2 C36.2 C37.2 C39.1 C40.2 C42.2 C43.2 C44.2 C45.1 C87.2 J4.3 Q1.1(S1) R7.2 R47.1 U2.104(VSS_PAD) U2.A25(N.C.) U2.B12(N.C.) U2.B26(N.C.) U2.G1(N.C.) U2.H2(N.C.) U2.J31(N.C.) X3.2(GND) X3.4(GND)
VBUS: J4.5 R5.2
VDD:DBGR: C17.1 C18.1 C20.1 C22.1 C31.1 C34.1 C35.1 C36.1 C37.1 C40.1 J4.1 R6.2 TP3.1 U2.A19(VDD) U2.AC1(VDD) U2.AG1(VDD) U2.AJ31(VDD) U2.AL3(VDD) U2.AL7(VDD) U2.AL11(VDD) U2.AL17(VDD) U2.AL25(VDD) U2.B8(VDD) U2.B28(VDD) U2.C1(VDD) U2.E31(VDD) U2.L1(VDD) U2.N31(VDD) U2.U1(VDD)
VDD:IO: R46.2
DBGR_BUTTON: U2.AL27(P0.24) ; port DBGR_BUTTON
DBGR_LED: Q1.2(G1) U2.AL29(P0.26/AIN5)
DBGR_N: U2.B4(D-) ; port USB_DBGR.D-
DBGR_P: U2.B2(D+) ; port USB_DBGR.D+
DBGR_RESET: J4.10 R6.1 TP4.1 U2.AC31(~{RESET})
DBGR_SWDCLK: J4.4 TP6.1 U2.W31(SWDCLK)
DBGR_SWDIO: J4.2 TP5.1 U2.AA31(SWDIO)
LED_PWR_CTRL: U2.A17(P1.13) ; port LED_PWR_CTRL
SWD0_CLK: U2.B18(P1.12) ; port SWD0.SWDCLK
SWD0_IO: U2.B16(P1.14) ; port SWD0.SWDIO
SWD0_RESET: U2.B22(P0.31) ; port SWD0.RESET
SWD0_SEL: U2.B24(P0.30) ; port SWD0.SELECT
SWD0_SWO: U2.B20(P1.11) ; port SWD0.SWO
SWD3_CLK: U2.R1(P0.01/XL2) ; port SWD3.SWDCLK
SWD3_CTRL: U2.AB2(P0.06/AIN2) ; port SWD3.SELECT
SWD3_IO: U2.N1(P0.00/XL1) ; port SWD3.SWDIO
SWD3_RESET: U2.AA1(P0.03/NFC2) ; port SWD3.RESET
SWD3_SWO: U2.W1(P0.02/NFC1) ; port SWD3.SWO
SWO_CTRL: U2.AJ1(P0.09/TRACEDATA[2]) ; port SWO_CTRL
TWI0_SCL: U2.AF2(P1.03/TWI) ; port TWI0.SCL
TWI0_SDA: U2.AE1(P1.02/TWI) ; port TWI0.SDA
UART0_CTRL: U2.R31(P1.10) ; port UART0_DBGR.CTRL
UART0_CTS: U2.AL9(P0.16/QSPI[3]) ; port UART0_DBGR.CTS
UART0_HWFC: U2.AK16(P0.20) ; port UART0_DBGR.HWFC
UART0_RTS: U2.AL5(P0.13/QSPI[0]) ; port UART0_DBGR.RTS
UART0_RxD: U2.AL19(P1.04) ; port UART0_DBGR.RXD
UART0_TxD: U2.U31(P0.29) ; port UART0_DBGR.TXD
UART1_CTRL: U2.AK18(P0.22) ; port UART1_DBGR.CTRL
UART1_CTS: U2.AL15(P0.21) ; port UART1_DBGR.CTS
UART1_HWFC: U2.AK20(P0.23) ; port UART1_DBGR.HWFC
UART1_RTS: U2.AL13(P0.19) ; port UART1_DBGR.RTS
UART1_RxD: U2.AL21(P1.06) ; port UART1_DBGR.RXD
UART1_TxD: U2.AL23(P1.08) ; port UART1_DBGR.TXD
VMEAS_CH1: C87.1 R46.1 R47.2 U2.V2(P0.04/AIN0)
NetC32_2: C32.2 C33.1 U2.A27(DECR) U2.G31(DECRF)
NetC39_2: C39.2 U2.A15(DECD)
NetC42_1: C42.1 R40.1 U2.A5(VBUS) U2.E1(VDDH)
NetC43_1: C43.1 U2.B6(DECUSB)
NetC44_1: C44.1 U2.A23(DECN)
NetC45_2: C45.2 U2.A13(DECA)
NetLD1_1: LD1.1(C) Q1.6(D1)
NetLD1_2: LD1.2(A) R5.1
NetR7_1: R7.1 U2.L31(ANT)
NetU2_B30: U2.B30(XC2) X3.3(out)
NetU2_C31: U2.C31(XC1) X3.1(inp)

Not connected (* = marked no-connect by the designer): J4 6 7 8 9; U2 A1(N.C.)* A21(DCC) A31(N.C.)* AD2(P0.07/AIN3) AE31(P0.28/AIN7)* AG31(N.C.)* AH2(P0.08/TRACEDATA[3]) AK2(P0.10/TRACEDATA[1]) AK4(P0.11/TRACEDATA[0]) AK6(P0.12/TRACECLK) AK8(P0.14/QSPI[1]) AK10(P0.15/QSPI[2]) AK12(P0.17/QSPI_CLK) AK14(P0.18/QSPI_CS) AK22(P1.05) AK24(P1.07) AK26(P1.09) AK28(P0.25/AIN4) AK30(P0.27/AIN6) AL1(N.C.)* AL31(N.C.)* B10(DCCD) B14(P1.15)* D2(N.C.)* F2(N.C.)* J1(DCCH) M2(P1.00) P2(P1.01) T2(N.C.)* Y2(P0.05/AIN1)

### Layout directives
differential pair; differential pair class IMCU; net class IMCU_USB: DBGR_N, DBGR_P

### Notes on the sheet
- nRF5340 is self powered through VBUS and VDDH
- Ports
- nRF54_PM_SEL

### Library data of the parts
C17 C18 C20 C22 C34-C37 C44 = C0201-100n: Capacitor, X5R, ±10%; Manufacturer: N.A.; Part number IPS: 00000001248, 00000002505; Part number Norautron: 262071862; Part number NEMS: 100200078; Pad Count: 2; Note: 16V; Component Status: Active
C31 C32 C39 C45 = C0402-1µ0-6.3V-X5R-10%: Capacitor, X5R, ±10%, 6.3V; Manufacturer: N.A.; Part number Norautron: 26207137; Part number NEMS: 100200498; Pad Count: 2; Component Status: Active
C33 = C0201-2n2: Capacitor, X7R, ±10%, 10V; Manufacturer: N.A.; Part number IPS: 00000001778; Part number Norautron: 26470002; Part number NEMS: 100200060; Pad Count: 2; Component Status: Active
C40 = C0603-2µ2-6.3V-X7R: Capacitor, X7R, ±10%, 6.3V; Manufacturer: N.A.; Part number NEMS: 100200272; Artikkelnr Noca: 20039322; Pad Count: 2; Component Status: Active
C42 C43 = C0603-4µ7-10V-X7S: Capacitor, X7S, ±10%, 10V; Manufacturer: N.A.; Part number IPS: 00000001779; Part number NEMS: 100200351; Pad Count: 2; Artikkelnr Noca: 20030013; Component Status: Active
C87 = C0201-10n: Capacitor, X7R, ±10%; Manufacturer: N.A.; Part number IPS: 00000003480; Part number Norautron: 26621779; Part number NEMS: 100200067; Note: 10V; Pad Count: 2; Component Status: Active
J4 = TC2050-IDC-NLFP: CBL PLUG-OF-NAILS 10-PIN; Manufacturer: Tag-Connect LLC; Part number NEMS: 100500463; Artikkelnr Noca: N.A.; Pad Count: 10; Component Status: Active; System: Connector
LD1 = VS 25C7M5: LED, Green, 0603, 573nm, Vf=2.0V, 24mcd, - 40 to +85°C; Manufacturer: Victory Electronics; Part number IPS: 00000001274, 00000009961; Part number Norautron: 26313411; Part number NEMS: 101400097; Pad Count: 2; Note: N.A.; Artikkelnr Noca: 13019193; Component Status: Active
Q1 = NX138AKS: MOSFET 2N-CH 60V 0.17A TSSOP6 (SOT363); Manufacturer: Nexperia; Manufacturer Part Number: NX138AKSX; Part number NEMS: 101300207; Component Status: Active; Pad Count: 6; Note: N.A.
R5 = R0201-560: Resistor, ±1%, 0.05W; Manufacturer: N.A.; Part number IPS: 00000007447; Part number NEMS: 100100038; Note: Chip Res 1%; Pad Count: 2; Component Status: Active
R6 = R0201-100k: Resistor, ±1%, 0.05W; Manufacturer: N.A.; Part number IPS: 00000001419; Part number Norautron: 26108487; Part number NEMS: 100100080; Note: Chip Res 1%; Pad Count: 2; Component Status: Active
R7 = R0201-47R: Resistor, ±1%, 0.05W; Manufacturer: N.A.; Part number IPS: 00000004794; Part number Norautron: 26108300; Part number NEMS: 100100022; Component Status: Active; Pad Count: 2; Note: Chip Res 1%
R40 = R0402-2R2: Resistor, ±1%, 0.063W; Manufacturer: N.A.; Part number IPS: 00000001796; Part number Norautron: 26470034; Part number NEMS: 100100116; Pad Count: 2; Note: Chip Res 1%; Artikkelnr Noca: 27049009; Component Status: Active
R46 R47 = R0201-10k: Resistor, ±1%, 0.05W; Manufacturer: N.A.; Part number IPS: 00000001255; Part number Norautron: 26107101; Part number NEMS: 100100065; Component Status: Active; Pad Count: 2; Note: Chip Res 1%
TP3-TP6 = TP_SMD_Ø1.5MM: 1.5mm circular SMD testpad; Manufacturer: Nordic Semiconductor; Manufacturer Part Number: N.A.; Part number NEMS: 100500477; Pad Count: 1; Component Status: Active
U2 = nRF5340-QKAA: Multi-protocol Bluetooth Low Energy, IEEE 802.15.4, ANT and 2.4GHz proprietary system-on-chip; Manufacturer: Nordic Semiconductor; Part number NEMS: 102000153; Pad Count: 98; Note: N.A.; Component Status: Active
X3 = XTAL_SMD2016_32MHz_8pF_Golledge: XTAL SMD 2016, 32MHz, Cl=8pF, Tol: ±10ppm, Stab: ±15ppm; Manufacturer Part Number: MP06003; Part number IPS: 00000001431; Part number Norautron: N.A.; Part number NEMS: 101600041,101600118; Component Status: Active; Pad Count: 4; Note: XTAL SMD 32.000MHz; Artikkelnr Noca: 22010050

## Sheet pca10188_sheet4_level_shifters.SchDoc: =BoardTitle+' - Level Shifters'
size A3; Organization: Nordic Semiconductor; DocumentNumber: 4; Revision: 0.7.0; SheetNumber: 4; SheetTotal: 7; Author: DABA; CompanyName: Nordic Semiconductor; DrawnBy: DABA; DocumentSize: A4
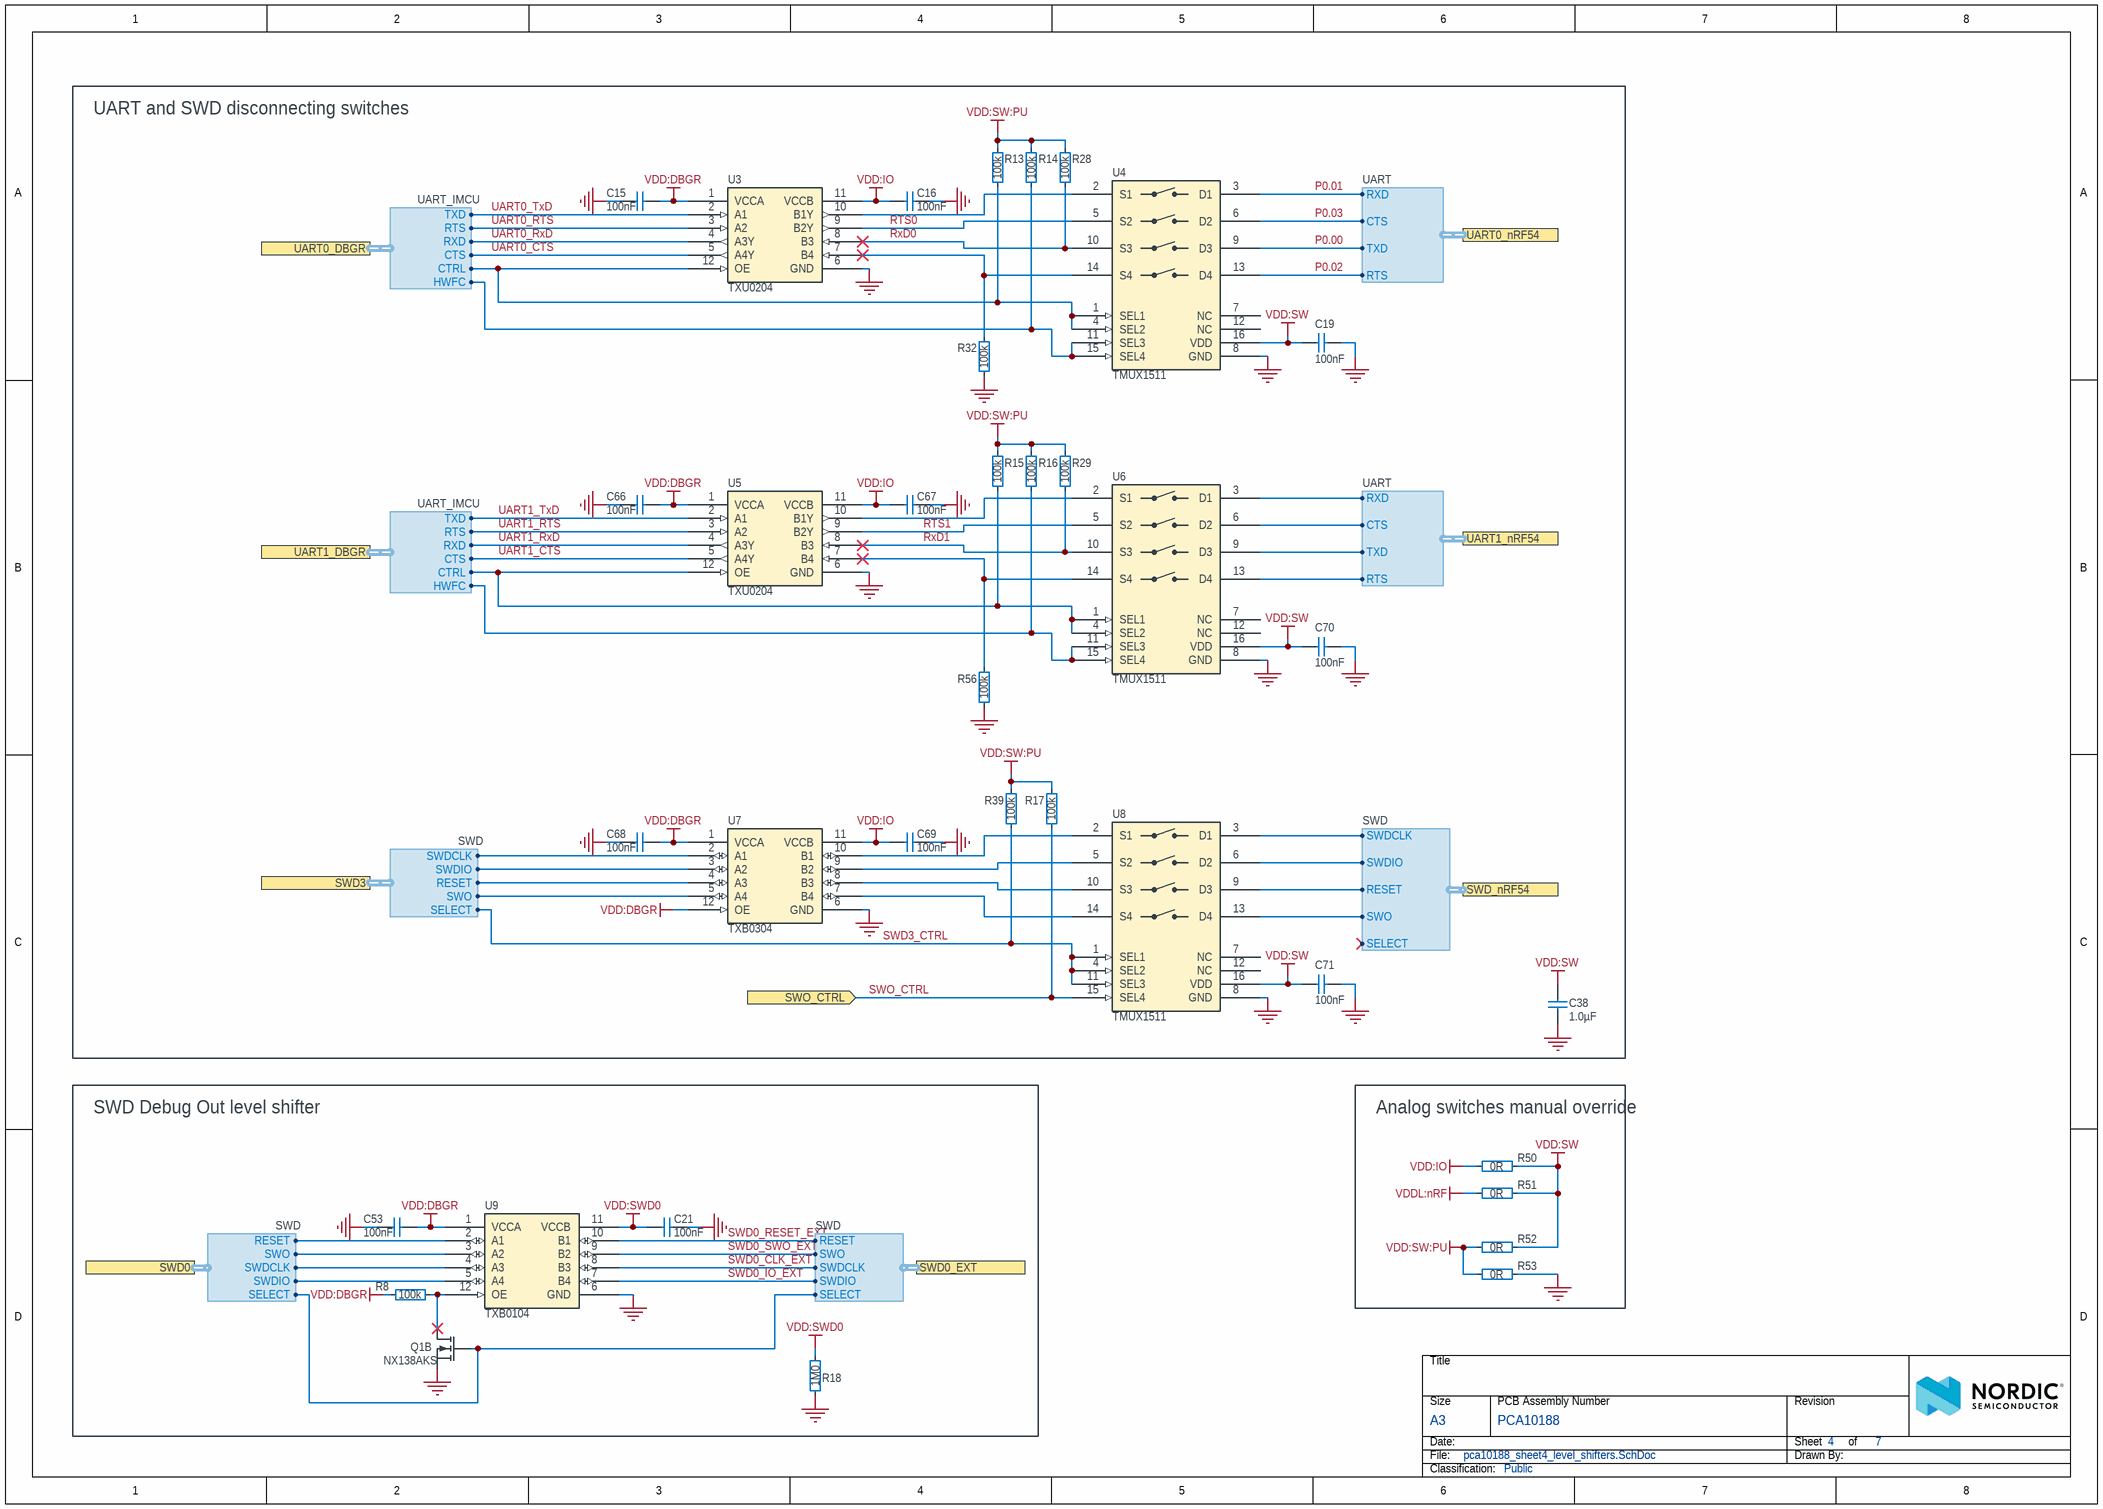
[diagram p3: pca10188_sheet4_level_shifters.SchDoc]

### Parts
C15  100nF  [CAPC0603X03L_C]
C16  100nF  [CAPC0603X03L_C]
C19  100nF  [CAPC0603X03L_C]
C21  100nF  [CAPC0603X03L_C]
C38  1.0µF  [CAPC1005X04L]
C53  100nF  [CAPC0603X03L_C]
C66  100nF  [CAPC0603X03L_C]
C67  100nF  [CAPC0603X03L_C]
C68  100nF  [CAPC0603X03L_C]
C69  100nF  [CAPC0603X03L_C]
C70  100nF  [CAPC0603X03L_C]
C71  100nF  [CAPC0603X03L_C]
Q1  NX138AKS  [TSSOP6]  (part B of 2)
R8  100k  [RESC0603X03L_C]
R13  100k  [RESC0603X03L_C]
R14  100k  [RESC0603X03L_C]
R15  100k  [RESC0603X03L_C]
R16  100k  [RESC0603X03L_C]
R17  100k  [RESC0603X03L_C]
R18  1M0  [RESC0603X03L_C]
R28  100k  [RESC0603X03L_C]
R29  100k  [RESC0603X03L_C]
R32  100k  [RESC0603X03L_C]
R39  100k  [RESC0603X03L_C]
R50  0R  [RESC1005X04L]
R51  0R  [RESC1005X04L]
R52  0R  [RESC1005X04L]
R53  0R  [RESC1005X04L]
R56  100k  [RESC0603X03L_C]
U3  TXU0204  [QFN12P40_170X200X55L50X20]
U4  TMUX1511  [XQFN40P180X260X50-16N]
U5  TXU0204  [QFN12P40_170X200X55L50X20]
U6  TMUX1511  [XQFN40P180X260X50-16N]
U7  TXB0304  [QFN12P40_170X200X55L50X20]
U8  TMUX1511  [XQFN40P180X260X50-16N]
U9  TXB0104  [QFN12P40_170X200X55L50X20]

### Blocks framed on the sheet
UART and SWD disconnecting switches: C15 C16 C19 C38 C66-C71 R13-R17 R28 R29 R32 R39 R56 U3-U8
SWD Debug Out level shifter: C21 C53 Q1 R8 R18 U9
Analog switches manual override: R50-R53

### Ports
SWD0 (harness SWD), SWD0_EXT (harness SWD), SWD3 (harness SWD), SWD_nRF54 (harness SWD), SWO_CTRL (in), UART0_DBGR (harness UART_IMCU), UART0_nRF54 (harness UART), UART1_DBGR (harness UART_IMCU), UART1_nRF54 (harness UART)

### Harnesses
SWD: SWDIO, SWDCLK, SWO, RESET, SELECT
UART_IMCU: RTS, CTS, RXD, TXD, HWFC, CTRL
UART: RTS, CTS, RXD, TXD

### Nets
GND: C15.1 C16.2 C19.2 C21.2 C38.1 C53.1 C66.1 C67.2 C68.1 C69.2 C70.2 C71.2 Q1.4(S2) R18.1 R32.2 R53.2 R56.2 U3.6(GND) U4.8(GND) U5.6(GND) U6.8(GND) U7.6(GND) U8.8(GND) U9.6(GND)
VDD:DBGR: C15.2 C53.2 C66.2 C68.2 R8.2 U3.1(VCCA) U5.1(VCCA) U7.1(VCCA) U7.12(OE) U9.1(VCCA)
VDD:IO: C16.1 C67.1 C69.1 R50.1 U3.11(VCCB) U5.11(VCCB) U7.11(VCCB)
VDD:SW: C19.1 C38.2 C70.1 C71.1 R50.2 R51.2 R52.2 U4.16(VDD) U6.16(VDD) U8.16(VDD)
VDD:SW:PU: R13.1 R14.1 R15.1 R16.1 R17.1 R28.1 R29.1 R39.1 R52.1 R53.1
VDD:SWD0: C21.1 R18.2 U9.11(VCCB)
VDDL:nRF: R51.1
nRF54_NRESET: U8.9(D3) ; port SWD_nRF54.RESET
P0.00: U4.9(D3) ; port UART0_nRF54.TXD
P0.01: U4.3(D1) ; port UART0_nRF54.RXD
P0.02: U4.13(D4) ; port UART0_nRF54.RTS
P0.03: U4.6(D2) ; port UART0_nRF54.CTS
P1.04: U6.9(D3) ; port UART1_nRF54.TXD
P1.05: U6.3(D1) ; port UART1_nRF54.RXD
P1.06: U6.13(D4) ; port UART1_nRF54.RTS
P1.07: U6.6(D2) ; port UART1_nRF54.CTS
P1.11: U8.13(D4) ; port SWD_nRF54.SWO
RTS0: U3.9(B2Y) U4.5(S2)
RTS1: U5.9(B2Y) U6.5(S2)
RxD0: R28.2 U3.8(B3) U4.10(S3)
RxD1: R29.2 U5.8(B3) U6.10(S3)
SWD0_CLK: U9.4(A3) ; port SWD0.SWDCLK
SWD0_CLK_EXT: U9.8(B3) ; port SWD0_EXT.SWDCLK
SWD0_IO: U9.5(A4) ; port SWD0.SWDIO
SWD0_IO_EXT: U9.7(B4) ; port SWD0_EXT.SWDIO
SWD0_RESET: U9.2(A1) ; port SWD0.RESET
SWD0_RESET_EXT: U9.10(B1) ; port SWD0_EXT.RESET
SWD0_SEL: Q1.5(G2) ; port SWD0.SELECT, port SWD0_EXT.SELECT
SWD0_SWO: U9.3(A2) ; port SWD0.SWO
SWD0_SWO_EXT: U9.9(B2) ; port SWD0_EXT.SWO
SWD3_CLK: U7.2(A1) ; port SWD3.SWDCLK
SWD3_CTRL: R39.2 U8.1(SEL1) U8.4(SEL2) U8.11(SEL3) ; port SWD3.SELECT
SWD3_IO: U7.3(A2) ; port SWD3.SWDIO
SWD3_RESET: U7.4(A3) ; port SWD3.RESET
SWD3_SWO: U7.5(A4) ; port SWD3.SWO
SWDCLK: U8.3(D1) ; port SWD_nRF54.SWDCLK
SWDIO: U8.6(D2) ; port SWD_nRF54.SWDIO
SWO_CTRL: R17.2 U8.15(SEL4) ; port SWO_CTRL
UART0_CTRL: R13.2 U3.12(OE) U4.1(SEL1) U4.4(SEL2) ; port UART0_DBGR.CTRL
UART0_CTS: U3.5(A4Y) ; port UART0_DBGR.CTS
UART0_HWFC: R14.2 U4.11(SEL3) U4.15(SEL4) ; port UART0_DBGR.HWFC
UART0_RTS: U3.3(A2) ; port UART0_DBGR.RTS
UART0_RxD: U3.4(A3Y) ; port UART0_DBGR.RXD
UART0_TxD: U3.2(A1) ; port UART0_DBGR.TXD
UART1_CTRL: R15.2 U5.12(OE) U6.1(SEL1) U6.4(SEL2) ; port UART1_DBGR.CTRL
UART1_CTS: U5.5(A4Y) ; port UART1_DBGR.CTS
UART1_HWFC: R16.2 U6.11(SEL3) U6.15(SEL4) ; port UART1_DBGR.HWFC
UART1_RTS: U5.3(A2) ; port UART1_DBGR.RTS
UART1_RxD: U5.4(A3Y) ; port UART1_DBGR.RXD
UART1_TxD: U5.2(A1) ; port UART1_DBGR.TXD
NetQ1_3: Q1.3(D2) R8.1 U9.12(OE)
NetR32_1: R32.1 U3.7(B4) U4.14(S4)
NetR56_1: R56.1 U5.7(B4) U6.14(S4)
NetU3_10: U3.10(B1Y) U4.2(S1)
NetU5_10: U5.10(B1Y) U6.2(S1)
NetU7_7: U7.7(B4) U8.14(S4)
NetU7_8: U7.8(B3) U8.10(S3)
NetU7_9: U7.9(B2) U8.5(S2)
NetU7_10: U7.10(B1) U8.2(S1)

Not connected (* = marked no-connect by the designer): U4 7(NC) 12(NC); U6 7(NC) 12(NC); U8 7(NC) 12(NC)

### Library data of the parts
C15 C16 C19 C21 C53 C66-C71 = C0201-100n: as C17 on sheet pca10188_sheet3_debugger
C38 = C0402-1µ0-6.3V-X5R-10%: as C31 on sheet pca10188_sheet3_debugger
Q1 = NX138AKS: as Q1 on sheet pca10188_sheet3_debugger
R8 R13-R17 R28 R29 R32 R39 R56 = R0201-100k: as R6 on sheet pca10188_sheet3_debugger
R18 = R0201-1M0: Resistor, ±1%, 0.05W; Manufacturer: N.A.; Part number IPS: 00000001418; Part number Norautron: 26107108; Part number NEMS: 100100093; Component Status: Active; Pad Count: 2; Note: Chip Res 1%
R50-R53 = R0402-0R: Resistor, ±5%, 0.063W; Manufacturer: N.A.; Part number IPS: 00000007128; Part number NEMS: 100100109; Component Status: Active; Pad Count: 2; Note: Chip Res 5%; Artikkelnr Noca: 27049000
U3 U5 = TXU0204RUTR: 4-Bit Fixed Direction Voltage-Level Translator with Schmitt-Trigger Inputs and 3-State Outputs; Manufacturer: Texas Instruments; Part number NEMS: 101900849; Component Status: Active; Pad Count: 12; Note: Translator, Multidirectional; Artikkelnr Noca: N.A.
U4 U6 U8 = TMUX1511: Low-Capacitance, 1:1 (SPST) 4-Channel, analog switch; Manufacturer: Texas Instruments; Manufacturer Part Number: TMUX1511RSVR; Part number NEMS: 101900847; Component Status: Active; Pad Count: 16; Note: N.A.
U7 = TXB0304RUTR: 4-Bit Bidirectional Level-Shifter/Voltage Translator with Automatic Direction Sensing; Manufacturer: Texas Instruments; Part number NEMS: 101900199; Component Status: Active; Pad Count: 12; Note: Translator, Bidirectional; Artikkelnr Noca: N.A.
U9 = TXB0104RUTR: 4-Bit Bidirectional Level-Shifter/Voltage Translator with Automatic Direction Sensing; Manufacturer: Texas Instruments; Part number NEMS: 101900856; Component Status: Active; Pad Count: 12; Note: Translator, Bidirectional; Artikkelnr Noca: N.A.

## Sheet pca10188_sheet5_misc.SchDoc: =BoardTitle+' - Misc'
size A3; Organization: Nordic Semiconductor; DocumentNumber: 5; Revision: 0.7.0; SheetNumber: 5; SheetTotal: 7; Author: DABA; CompanyName: Nordic Semiconductor; DrawnBy: DABA; DocumentSize: A4
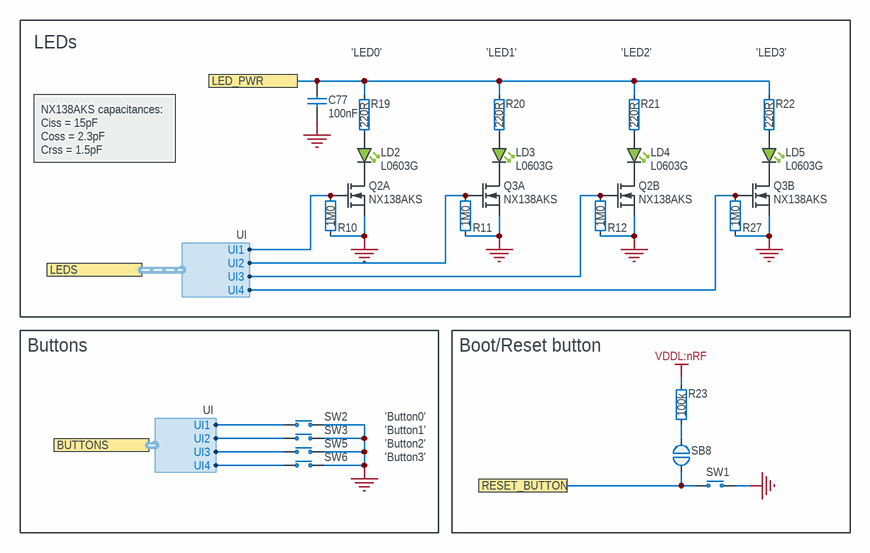
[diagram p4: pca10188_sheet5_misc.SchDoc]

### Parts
C77  100nF  [CAPC0603X03L_C]
LD2  L0603G  [LED_0603_G]
LD3  L0603G  [LED_0603_G]
LD4  L0603G  [LED_0603_G]
LD5  L0603G  [LED_0603_G]
Q2  NX138AKS  [TSSOP6]  (parts A,B of 2)
Q3  NX138AKS  [TSSOP6]  (parts A,B of 2)
R10  1M0  [RESC0603X03L_C]
R11  1M0  [RESC0603X03L_C]
R12  1M0  [RESC0603X03L_C]
R19  220R  [RESC0603X03L_C]
R20  220R  [RESC0603X03L_C]
R21  220R  [RESC0603X03L_C]
R22  220R  [RESC0603X03L_C]
R23  100k  [RESC0603X03L_C]
R27  1M0  [RESC0603X03L_C]
SB8  Solderbridge  [Solderbridge]  (value not drawn)  (no BOM)
SW1  PB SW  [Switch-PB-6.2x6.3mm-SMD]  (value not drawn)
SW2  PB SW  [Switch-PB-6.2x6.3mm-SMD]  (value not drawn)
SW3  PB SW  [Switch-PB-6.2x6.3mm-SMD]  (value not drawn)
SW5  PB SW  [Switch-PB-6.2x6.3mm-SMD]  (value not drawn)
SW6  PB SW  [Switch-PB-6.2x6.3mm-SMD]  (value not drawn)

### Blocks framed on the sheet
LEDs: C77 LD2-LD5 Q2 Q3 R10-R12 R19-R22 R27
Buttons: SW2 SW3 SW5 SW6
Boot/Reset button: R23 SB8 SW1

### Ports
BUTTONS (harness UI), LED_PWR, LEDS (harness UI), RESET_BUTTON

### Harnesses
UI: UI2, UI1, UI3, UI4
UI: UI2, UI3, UI4, UI1

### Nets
GND: C77.1 Q2.1(S1) Q2.4(S2) Q3.1(S1) Q3.4(S2) R10.2 R11.2 R12.2 R27.2 SW1.1(N.O) SW2.1(N.O) SW3.1(N.O) SW5.1(N.O) SW6.1(N.O)
VDDL:nRF: R23.2
LED_PWR: C77.2 R19.2 R20.2 R21.2 R22.2 ; port LED_PWR
P0.04: SW6.2(COM) ; port BUTTONS.UI4
P1.08: SW5.2(COM) ; port BUTTONS.UI3
P1.09: SW3.2(COM) ; port BUTTONS.UI2
P1.10: Q3.2(G1) R11.1 ; port LEDS.UI2
P1.21: SW2.2(COM) ; port BUTTONS.UI1
P1.22: Q3.5(G2) R27.1 ; port LEDS.UI4
P1.24: Q2.2(G1) R10.1 ; port LEDS.UI1
P1.25: Q2.5(G2) R12.1 ; port LEDS.UI3
RESET_BUTTON: SB8.1 SW1.2(COM) ; port RESET_BUTTON
NetLD2_1: LD2.1(C) Q2.6(D1)
NetLD2_2: LD2.2(A) R19.1
NetLD3_1: LD3.1(C) Q3.6(D1)
NetLD3_2: LD3.2(A) R20.1
NetLD4_1: LD4.1(C) Q2.3(D2)
NetLD4_2: LD4.2(A) R21.1
NetLD5_1: LD5.1(C) Q3.3(D2)
NetLD5_2: LD5.2(A) R22.1
NetR23_1: R23.1 SB8.2

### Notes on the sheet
- 'LED0'
- (near R20) 'LED1'
- (near R21) 'LED2'
- (near R22) 'LED3'
- NX138AKS capacitances:
  Ciss = 15pF
  Coss = 2.3pF
  Crss = 1.5pF
- 'Button0'
- 'Button1'
- 'Button2'
- 'Button3'

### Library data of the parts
C77 = C0201-100n: Capacitor, X5R, ±10%; Manufacturer: N.A.; Part number IPS: 00000001248, 00000002505; Part number Norautron: 262071862; Part number NEMS: 100200078; Note: 16V; Pad Count: 2; Component Status: Active
LD2-LD5 = VS 25C7M5: as LD1 on sheet pca10188_sheet3_debugger
Q2 Q3 = NX138AKS: as Q1 on sheet pca10188_sheet3_debugger
R10-R12 R27 = R0201-1M0: as R18 on sheet pca10188_sheet4_level_shifters
R19-R22 = R0201-220: Resistor, ±1%, 0.05W; Manufacturer: N.A.; Part number IPS: 00000000863; Part number Norautron: 26107014; Part number NEMS: 100100032; Note: Chip Res 1%; Pad Count: 2; Component Status: Active
R23 = R0201-100k: as R6 on sheet pca10188_sheet3_debugger
SB8 = Solderbridge: as SB1 on sheet pca10188_sheet1_cover_sheet
SW1-SW3 SW5 SW6 = Switch-PB-6.2x6.3mm-SMD: Tactile Switch, SPNO, SMD, 160gf, 6.2x6.3x2.5mm; Manufacturer: Dailywell; Manufacturer Part Number: TS604VM1-025BR-R; Part number IPS: 00000007812; Part number NEMS: 101500001, 101500133; Note: N.A.; Artikkelnr Noca: 50019106; Pad Count: 4; Component Status: Active

## Sheet pca10188_sheet6_power_supply.SchDoc: =BoardTitle+' - Power Supply'
size A3; Organization: Nordic Semiconductor; DocumentNumber: 6; Revision: 0.7.0; SheetNumber: 6; SheetTotal: 7; Author: DABA; CompanyName: Nordic Semiconductor; DrawnBy: DABA; DocumentSize: A4
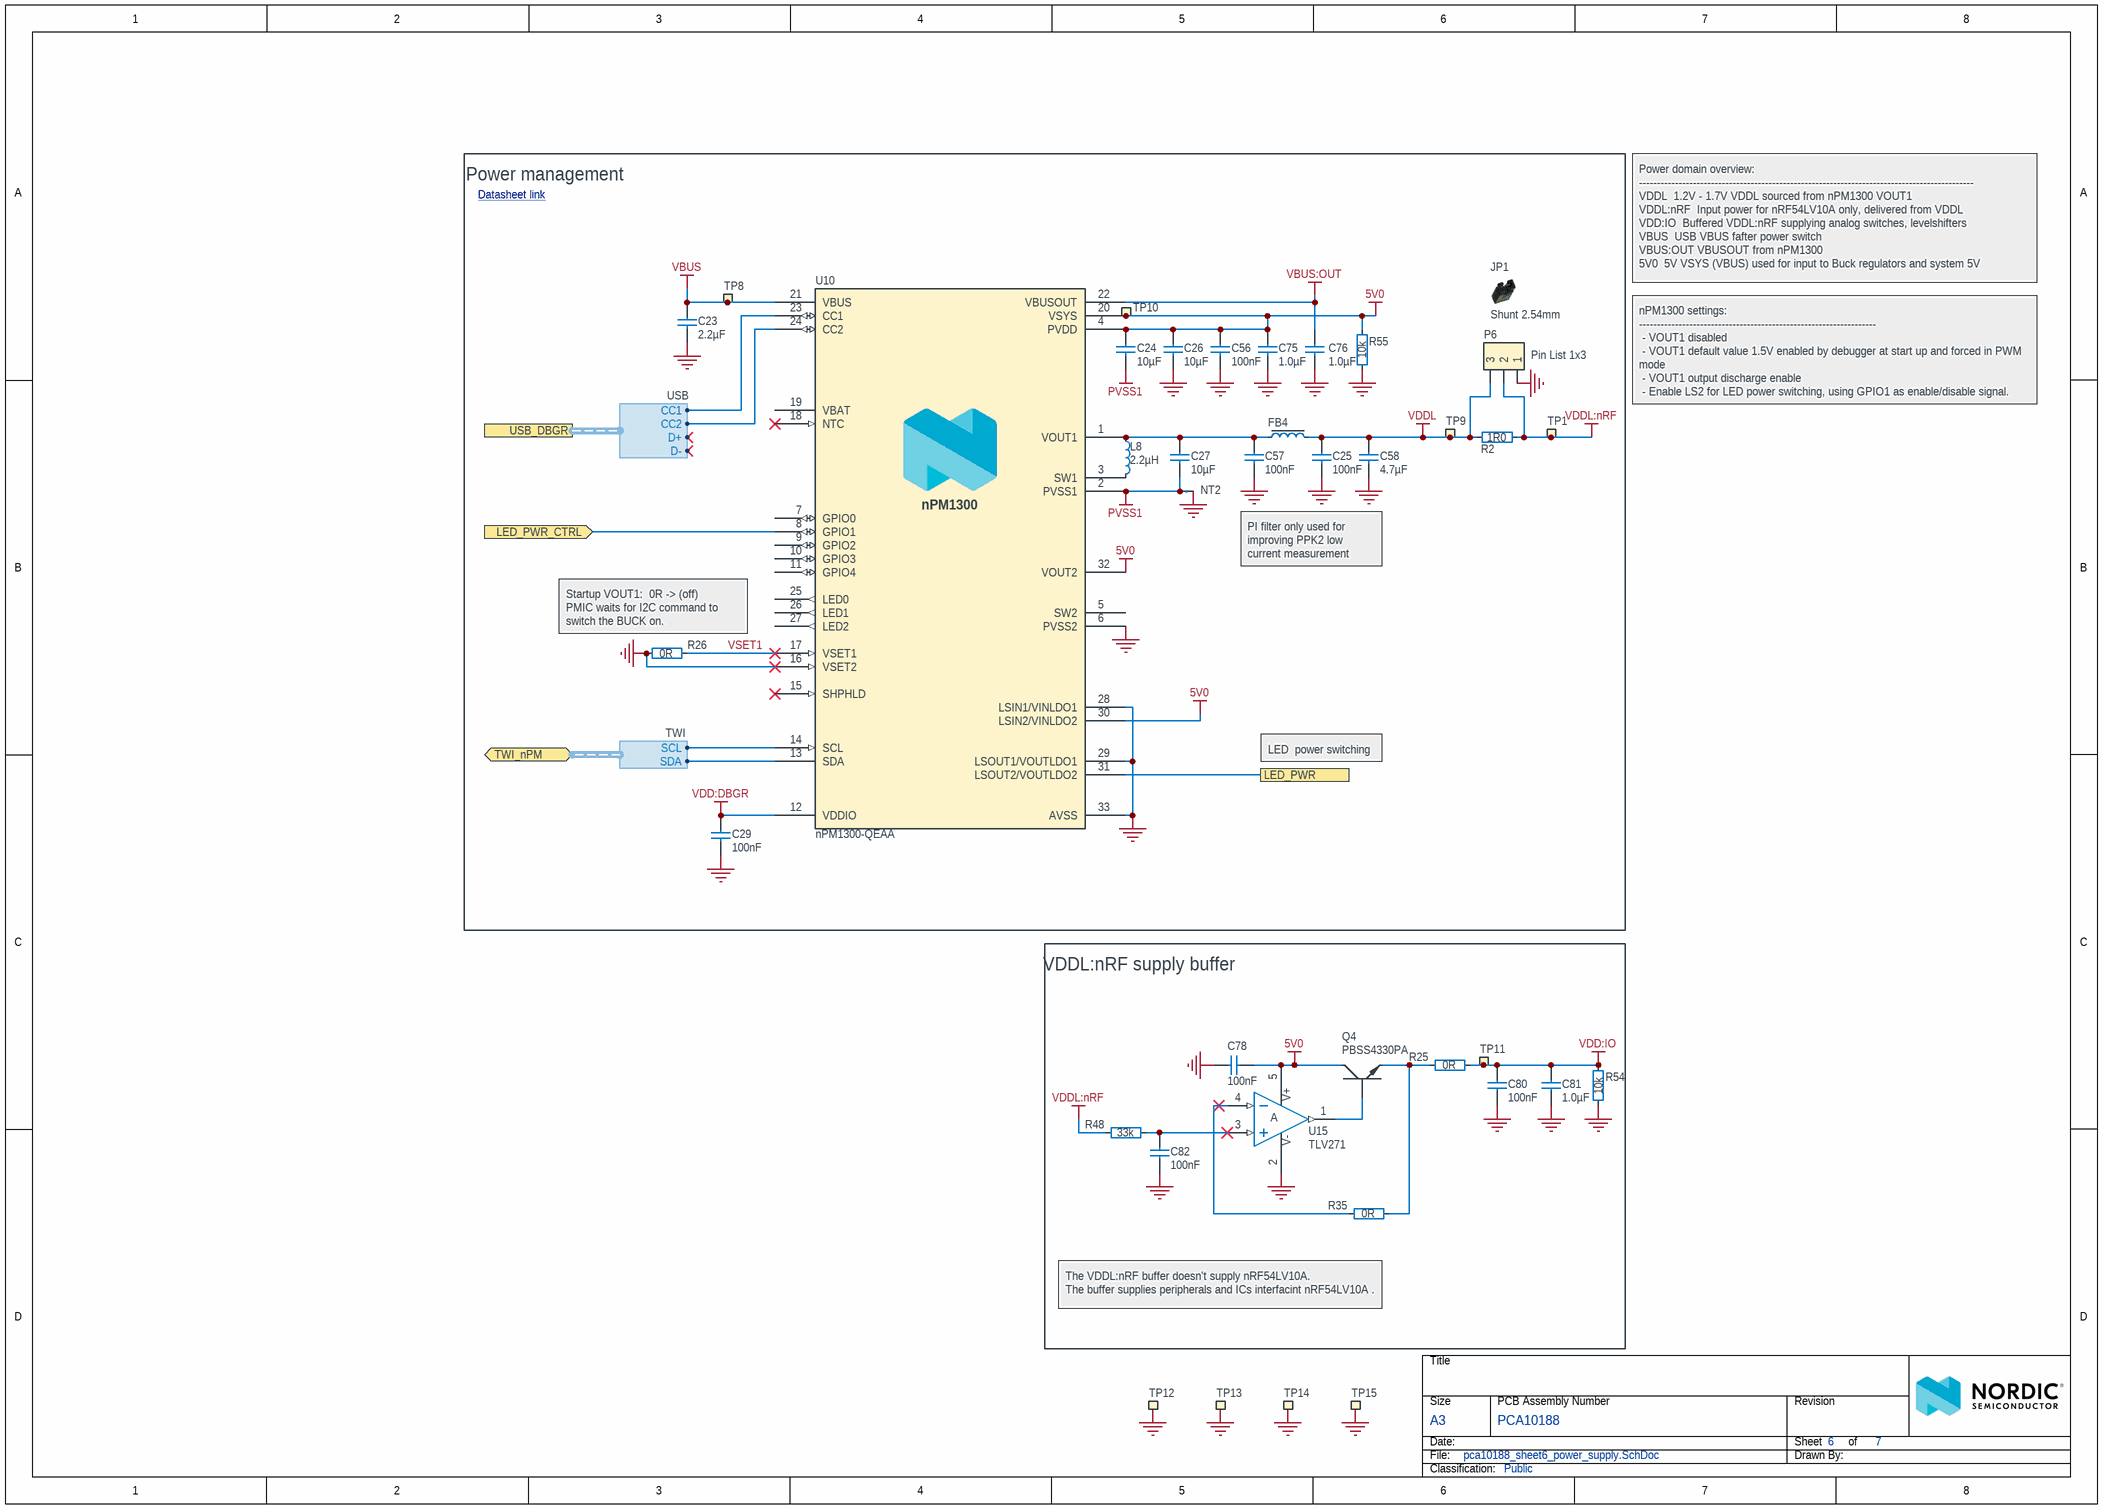
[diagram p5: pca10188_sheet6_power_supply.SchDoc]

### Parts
C23  2.2µF  [CAPC1005X04L]
C24  10µF  [CAPC1608X06L]
C25  100nF  [CAPC0603X03L_C]
C26  10µF  [CAPC1608X06L]
C27  10µF  [CAPC1608X06L]
C29  100nF  [CAPC0603X03L_C]
C56  100nF  [CAPC0603X03L_C]
C57  100nF  [CAPC0603X03L_C]
C58  4.7µF  [CAPC1608X06L]
C75  1.0µF  [CAPC1005X04L]
C76  1.0µF  [CAPC1005X04L]
C78  100nF  [CAPC0603X03L_C]
C80  100nF  [CAPC0603X03L_C]
C81  1.0µF  [CAPC1005X04L]
C82  100nF  [CAPC0603X03L_C]
FB4  120R/0.55A  [INDC1005X04L]  (value not drawn)
JP1  Shunt 2.54mm  [Shunt_2.54mm_Vertical]
L8  2.2µH  [INDC2016X10N]
NT2  Net tie  [2 PIN STARPOINT]  (value not drawn)  (net tie, no BOM)
P6  Pin List 1x3  [LIST_1x3_SMD]
Q4  PBSS4330PA  [DFN105P200X65-3N_v2]
R2  1R0  [RESC1005X04L]
R25  0R  [RESC0603X03L_C]
R26  0R  [RESC0603X03L_C]
R35  0R  [RESC0603X03L_C]
R48  33k  [RESC0603X03L_C]
R54  10k  [RESC1005X04L]
R55  10k  [RESC1005X04L]
TP1  Ø1.5mm,SMD  [TP_SMD_D1.5mm]  (value not drawn)  (no BOM)
TP8  Ø1.5mm,SMD  [TP_SMD_D1.5mm]  (value not drawn)  (no BOM)
TP9  Ø1.5mm,SMD  [TP_SMD_D1.5mm]  (value not drawn)  (no BOM)
TP10  Ø1.5mm,SMD  [TP_SMD_D1.5mm]  (value not drawn)  (no BOM)
TP11  Ø1.5mm,SMD  [TP_SMD_D1.5mm]  (value not drawn)  (no BOM)
TP12  Ø1.5mm,SMD  [TP_SMD_D1.5mm]  (value not drawn)  (no BOM)
TP13  Ø1.5mm,SMD  [TP_SMD_D1.5mm]  (value not drawn)  (no BOM)
TP14  Ø1.5mm,SMD  [TP_SMD_D1.5mm]  (value not drawn)  (no BOM)
TP15  Ø1.5mm,SMD  [TP_SMD_D1.5mm]  (value not drawn)  (no BOM)
U10  nPM1300-QEAA  [Nordic_QFN50P500X500X90-33N]
U15  TLV271  [SOT95P280X145-5N]

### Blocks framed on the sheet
Power management: C23-C27 C29 C56-C58 C75 C76 FB4 JP1 L8 NT2 P6 R2 R26 R55 TP1 TP8-TP10 U10
VDDL:nRF supply buffer: C78 C80-C82 Q4 R25 R35 R48 R54 TP11 U15

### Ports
LED_PWR, LED_PWR_CTRL (in), TWI_nPM (bidir, harness TWI), USB_DBGR (harness USB)

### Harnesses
TWI: SDA, SCL
USB: D+, D-, CC1, CC2

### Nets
5V0: C24.2 C26.2 C56.2 C75.2 C78.1 Q4.3(C) R55.2 TP10.1 U10.4(PVDD) U10.20(VSYS) U10.30(LSIN2/VINLDO2) U10.32(VOUT2) U15.5(VDD)
GND: C23.1 C25.1 C26.1 C29.2 C56.1 C57.1 C58.2 C75.1 C76.1 C78.2 C80.2 C81.1 C82.2 NT2.1 P6.1 R26.2 R54.1 R55.1 TP12.1 TP13.1 TP14.1 TP15.1 U10.6(PVSS2) U10.16(VSET2) U10.28(LSIN1/VINLDO1) U10.29(LSOUT1/VOUTLDO1) U10.33(AVSS) U15.2(VSS)
PVSS1: C24.1 C27.1 NT2.2 U10.2(PVSS1)
VBUS: C23.2 TP8.1 U10.21(VBUS)
VBUS:OUT: C76.2 U10.22(VBUSOUT)
VDD:DBGR: C29.1 U10.12(VDDIO)
VDD:IO: C80.1 C81.2 R25.2 R54.2 TP11.1
VDDL: C25.2 C58.1 FB4.2 P6.3 R2.2 TP9.1
VDDL:nRF: P6.2 R2.1 R48.1 TP1.1
LED_PWR: U10.31(LSOUT2/VOUTLDO2) ; port LED_PWR
LED_PWR_CTRL: U10.8(GPIO1) ; port LED_PWR_CTRL
TWI0_SCL: U10.14(SCL) ; port TWI_nPM.SCL
TWI0_SDA: U10.13(SDA) ; port TWI_nPM.SDA
VSET1: R26.1 U10.17(VSET1)
NetC27_2: C27.2 C57.2 FB4.1 L8.1 U10.1(VOUT1)
NetC82_1: C82.1 R48.2 U15.3(IN+)
NetJ3_A5: U10.23(CC1) ; port USB_DBGR.CC1
NetJ3_B5: U10.24(CC2) ; port USB_DBGR.CC2
NetL8_2: L8.2 U10.3(SW1)
NetQ4_1: Q4.1(B) U15.1(OUT)
NetQ4_2: Q4.2(E) R25.1 R35.2
NetR35_1: R35.1 U15.4(IN-)

Not connected (* = marked no-connect by the designer): U10 5(SW2) 7(GPIO0) 9(GPIO2) 10(GPIO3) 11(GPIO4) 15(SHPHLD)* 18(NTC)* 19(VBAT) 25(LED0) 26(LED1) 27(LED2)

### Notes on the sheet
- Datasheet link <https://docs.nordicsemi.com/bundle/ps_npm1300/>
- Power domain overview:
  ---------------------------------------------------------------------------------------------
  VDDL		1.2V - 1.7V VDDL sourced from nPM1300 VOUT1
  VDDL:nRF		Input power for nRF54LV10A only, delivered from VDDL
  VDD:IO		Buffered VDDL:nRF supplying analog switches, levelshifters
  VBUS		USB VBUS fafter power switch
  VBUS:OUT	VBUSOUT from nPM1300
  5V0		5V VSYS (VBUS) used for input to Buck regulators and system 5V
- nPM1300 settings:
  ------------------------------------------------------------------
  - VOUT1 disabled
  - VOUT1 default value 1.5V enabled by debugger at start up and forced in PWM mode
  - VOUT1 output discharge enable
  - Enable LS2 for LED power switching, using GPIO1 as enable/disable signal.
- PI filter only used for improving PPK2 low current measurement accuracy
- (near R26) Startup VOUT1:  0R -> (off)
  PMIC waits for I2C command to
  switch the BUCK on.
- LED  power switching
- (near R35) The VDDL:nRF buffer doesn't supply nRF54LV10A.
  The buffer supplies peripherals and ICs interfacint nRF54LV10A .

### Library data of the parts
C23 = C0402-2µ2-10V: Capacitor, X5R, ±10%; Manufacturer: N.A.; Part number NEMS: 100200376; Component Status: Active; Pad Count: 2; Note: 10V
C24 C26 C27 = C0603-10µ-10V-X7T-GRM188D71A106MA73: Capacitor, X7T, ±20%, 10V; Manufacturer: Murata; Manufacturer Part Number: GRM188D71A106MA73D; Part number IPS: 00000004696; Part number NEMS: 100200414; Component Status: Active; Pad Count: 2; Note: 10VDC; Artikkelnr Noca: N.A.
C25 C56 C57 = C0201-100n: as C77 on sheet pca10188_sheet5_misc
C29 C78 C80 C82 = C0201-100n: as C17 on sheet pca10188_sheet3_debugger
C58 = C0603-4µ7-10V-X7S: as C42 on sheet pca10188_sheet3_debugger
C75 C81 = C0402-1µ0-6.3V-X5R-10%: as C31 on sheet pca10188_sheet3_debugger
C76 = C0402-1µ0-10V-X5R: Capacitor, Ceramic, X5R, ±10%, 10V; Manufacturer: N.A.; Part number NEMS: 100200482; Component Status: Active; Pad Count: 2
FB4 = FB0402-120R@100M-500mA: Ferrite Bead, 120 Ohm @ 100MHz, 500mA, 250 mOhm Max; Manufacturer: Murata; Manufacturer Part Number: BLM15AG121SN1D; Part number IPS: 00000009954; Part number Norautron: 265230631; Part number NEMS: 100300099; Note: Chip EMIFIL Inductor Type Chip Ferrite Bead; Artikkelnr Noca: 33029317; Pad Count: 2; Component Status: Active
JP1 = SHUNT JUMPER 2.54mm Black Vertical: Shunt Jumper 2.54mm Black, open top; Manufacturer: WCON; Manufacturer Part Number: 3710-6001OS0B05; Part number NEMS: 100500728; Pad Count: 2; Note: N.A.; Component Status: Active; System: Connector
L8 = L0806-2µ2-2500mA-73mOhm-CIGT201610EH2R2MNE: Inductor, Irms=2.5A, Isat=2.9A, ±20%, DCR=73mΩ; Manufacturer: Samsung Electro-Mechanics America; Part number Norautron: 26521789; Part number NEMS: 100300400; Component Status: Active; Pad Count: 2; Note: Unshielded Thin Film Inductor; Artikkelnr Noca: N.A.
NT2 = 2 pin starpoint: Starpoint; Manufacturer: N.A.; Part number NEMS: 100500603; Pad Count: 2; Component Status: Active; System: Connector
P6 = Pin List 1x3 SMD: Pin List 1x3, 2.54mm (100mil), SMD; Manufacturer: WCON; Manufacturer Part Number: 1125-1103S0M116CR04; Part number Norautron: 26470016; Part number NEMS: 100500306; Note: N.A.; Pad Count: 3; Component Status: Active; System: Connector
Q4 = PBSS4330PA,115: 30V, 3A, 2.1W, G=270, NPN Transistor; Manufacturer: Nexperia; Part number NEMS: 101300184; Component Status: Active; Pad Count: 3; Note: N.A.
R2 = R0402-1R0: Resistor, ±1%, 0.063W; Manufacturer: N.A.; Part number IPS: 00000004795; Part number Norautron: 261080032; Part number NEMS: 100100112; Component Status: Active; Pad Count: 2; Note: Chip Res 1%; Artikkelnr Noca: 27049001
R25 R26 R35 = R0201-0R: Resistor, ±5%, 0.05W; Manufacturer: N.A.; Part number IPS: 00000003245; Part number NEMS: 100100001; Component Status: Active; Pad Count: 2; Note: Chip Res 5%
R48 = R0201-33k: Resistor, ±1%, 0.05W; Manufacturer: N.A.; Part number IPS: 00000001708; Part number NEMS: 100100073; Component Status: Active; Pad Count: 2; Note: Chip Res 1%
R54 R55 = R0402-10k: Resistor, ±1%, 0.063W; Manufacturer: N.A.; Part number IPS: 00000002093; Part number NEMS: 100100198; Component Status: Active; Pad Count: 2; Note: Chip Res 1%; Artikkelnr Noca: 27049097
TP1 TP8-TP15 = TP_SMD_Ø1.5MM: as TP3 on sheet pca10188_sheet3_debugger
U10 = nPM1300-QEAA: Li-Ion/Li-Polymer USB-C battery charger with high efficiency buck regulators, LDOs or load switches, LED drivers, TWI and VBUSOUT; Manufacturer: Nordic Semiconductor; Part number NEMS: 102000291; Component Status: Active; Pad Count: 33; Note: N.A.
U15 = TLV271CW5-7: Dual rail to rail CMOS Amplifier; Manufacturer: Diodes Incorporated; Part number NEMS: 101900398; Component Status: Active; Pad Count: 5; Note: N.A.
